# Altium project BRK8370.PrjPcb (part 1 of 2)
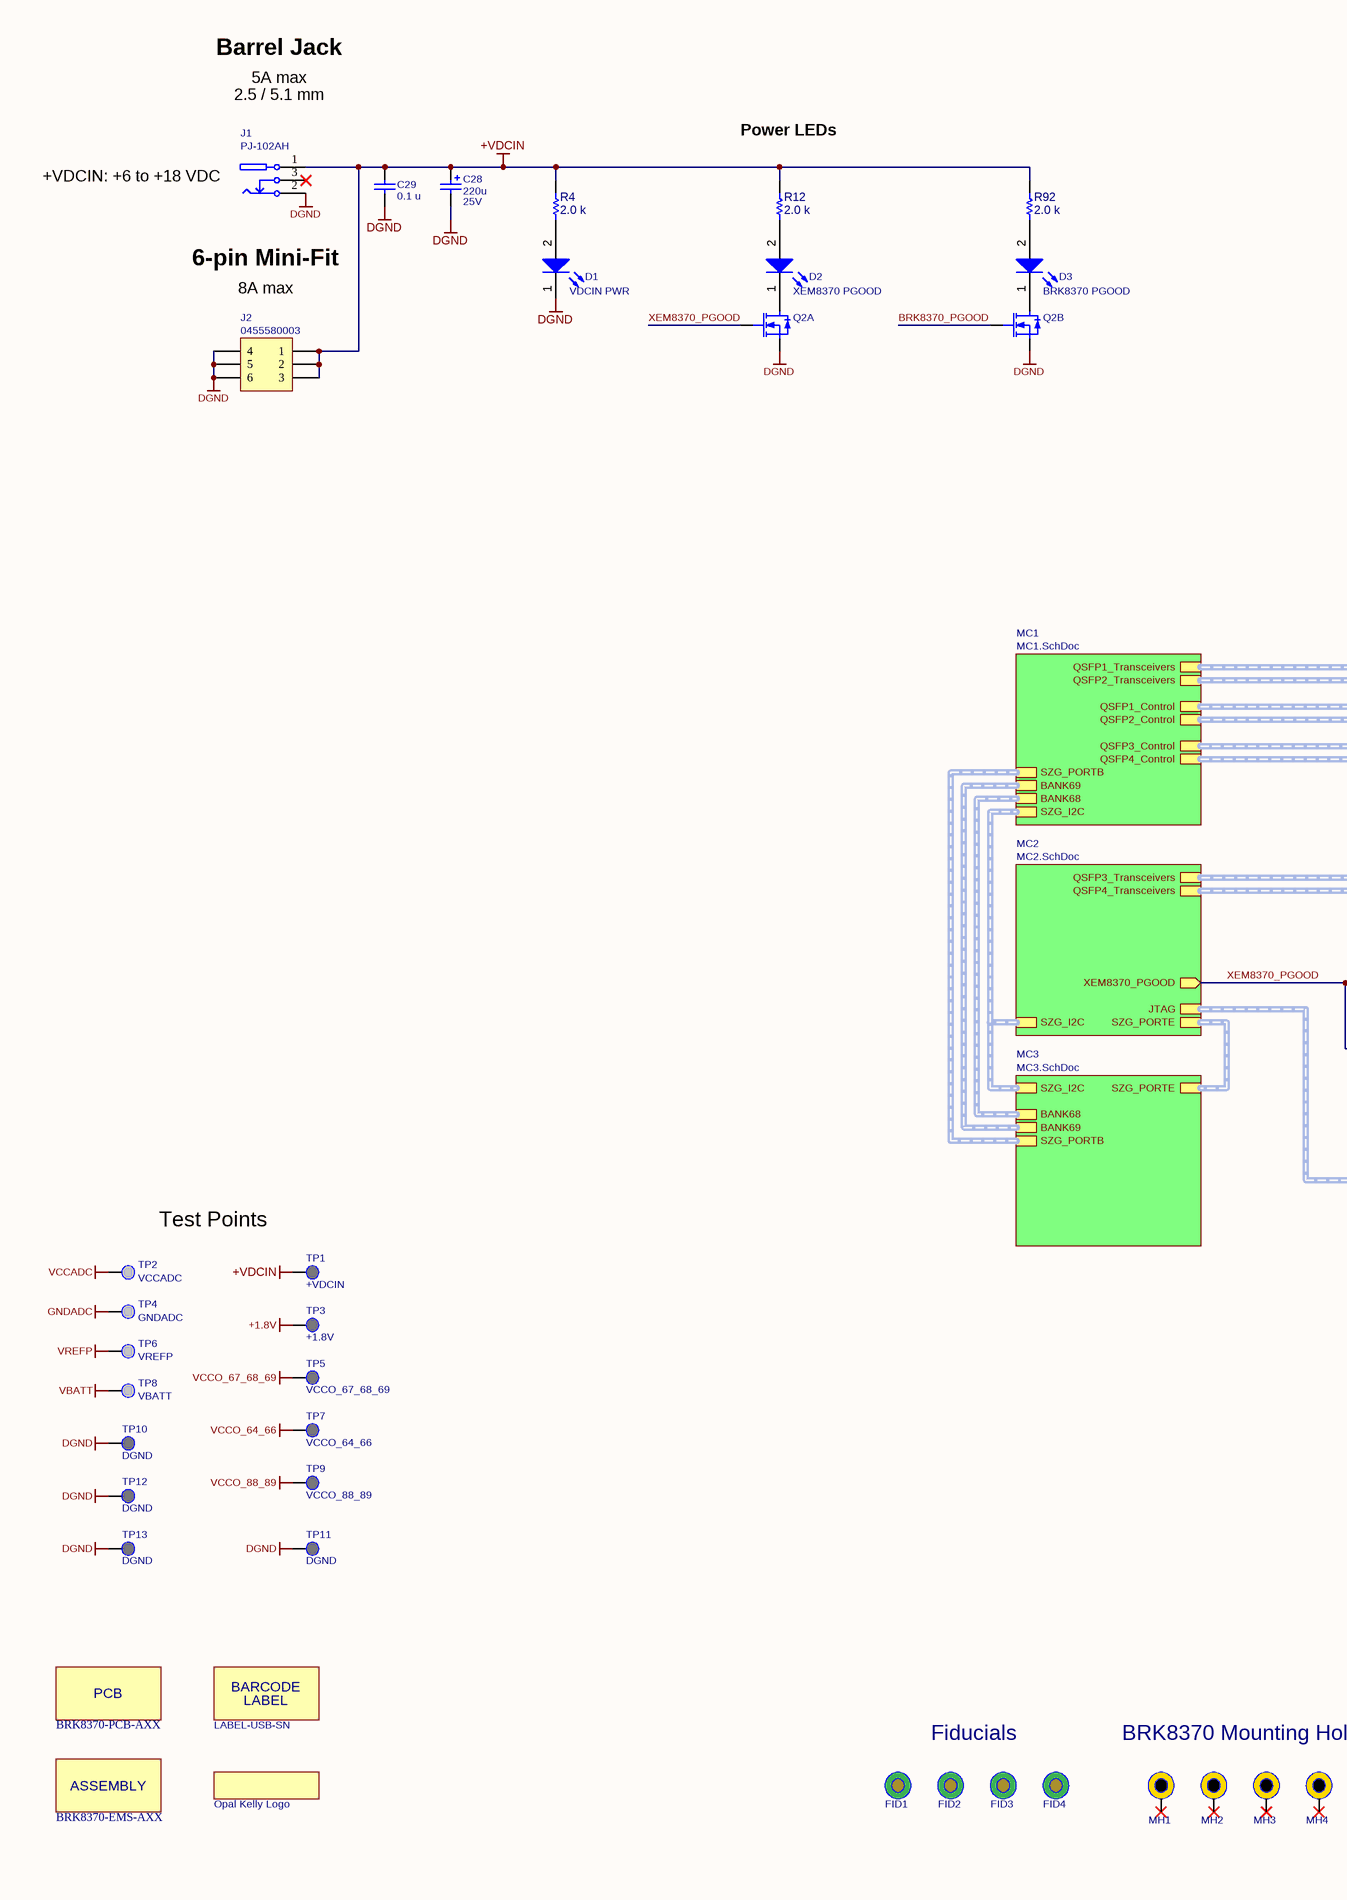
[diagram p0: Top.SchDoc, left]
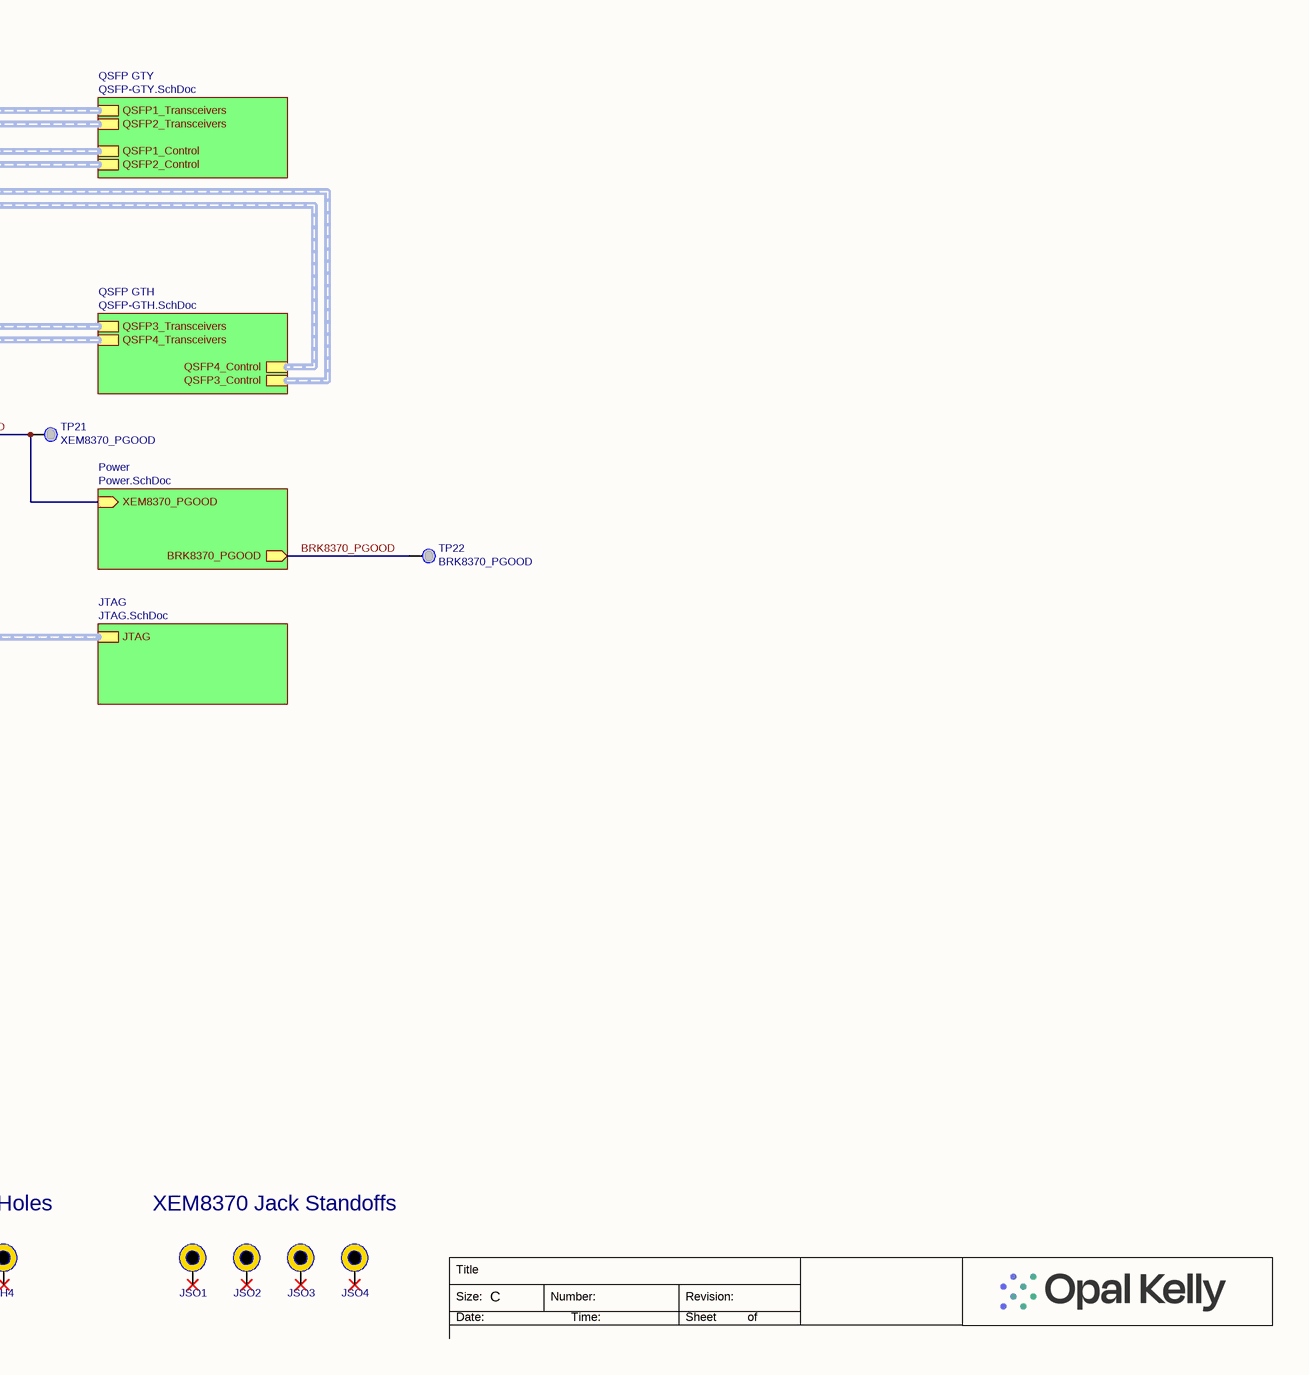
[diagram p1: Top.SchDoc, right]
PCB_Revision: A; Part_Number: BRK8370; BOM_Revision: 02
8 sheets, 322 parts. Net scope: hierarchical (ports join the sheet entries above them; power ports are global).
Board file: BRK8370.PcbDoc
Sheets:
  Top.SchDoc
    MC1 = MC1.SchDoc
    MC2 = MC2.SchDoc
    MC3 = MC3.SchDoc
    QSFP GTH = QSFP-GTH.SchDoc
    QSFP GTY = QSFP-GTY.SchDoc
    Power = Power.SchDoc
    JTAG = JTAG.SchDoc

## Sheet Top.SchDoc: BRK8370
size C; Organization: Opal Kelly; Address1: 13500 SW 72nd Ave STE 100; Address2: Portland, OR 97223; Address3: 217.391.3724; Address4: http://www.opalkelly.com; DocumentNumber: 1; Revision: 1; SheetNumber: 1; SheetTotal: 8

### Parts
ASSY1  BRK8370-EMS-AXX  (mechanical)
C28  value 220u  Voltage: 25V  [CAPAE9083X70N]  (hidden comment: EEE-FK1E221P)
C29  value 0.1 u  [CAPC1005X06A]  (hidden comment: TMK105BJ104KV-F)
D1  VDCIN PWR  [CD1608-0603-PIN1-CATHODE]
D2  XEM8370 PGOOD  [CD1608-0603-PIN1-CATHODE]
D3  BRK8370 PGOOD  [CD1608-0603-PIN1-CATHODE]
FID1  FIDUCIAL  [FID1MM/2MM-SS]  (value not drawn)
FID2  FIDUCIAL  [FID1MM/2MM-SS]  (value not drawn)
FID3  FIDUCIAL  [FID1MM/2MM-SS]  (value not drawn)
FID4  FIDUCIAL  [FID1MM/2MM-SS]  (value not drawn)
J1  PJ-102AH  [CUI-PJ102A]
J2  0455580003  [0455580003]
JSO1  Jack Screw Standoff  [JSO-0515-01]  (value not drawn)
JSO2  Jack Screw Standoff  [JSO-0515-01]  (value not drawn)
JSO3  Jack Screw Standoff  [JSO-0515-01]  (value not drawn)
JSO4  Jack Screw Standoff  [JSO-0515-01]  (value not drawn)
LABEL1  LABEL-USB-SN  (mechanical)
LOGO1  Opal Kelly Logo  [okLogo-23x5-2021]
MH1  MTG  [MTG-3.2/6.5-PTH]  (value not drawn)
MH2  MTG  [MTG-3.2/6.5-PTH]  (value not drawn)
MH3  MTG  [MTG-3.2/6.5-PTH]  (value not drawn)
MH4  MTG  [MTG-3.2/6.5-PTH]  (value not drawn)
PCB1  BRK8370-PCB-AXX  (mechanical)
Q2  SI1922EDH-T1-GE3  [SOT363-6N]  (value not drawn)  (parts A,B of 2)
R4  value 2.0 k  [RESC1005X06A]  (hidden comment: CRCW04022K00FKED)
R12  value 2.0 k  [RESC1005X06A]  (hidden comment: CRCW04022K00FKED)
R92  value 2.0 k  [RESC1005X06A]  (hidden comment: CRCW04022K00FKED)
TP1  +VDCIN  [TP-PTH-65/100]
TP2  VCCADC  [TP-PTH-25/45]
TP3  +1.8V  [TP-PTH-65/100]
TP4  GNDADC  [TP-PTH-25/45]
TP5  VCCO_67_68_69  [TP-PTH-65/100]
TP6  VREFP  [TP-PTH-25/45]
TP7  VCCO_64_66  [TP-PTH-65/100]
TP8  VBATT  [TP-PTH-25/45]
TP9  VCCO_88_89  [TP-PTH-65/100]
TP10  DGND  [TP-PTH-65/100]
TP11  DGND  [TP-PTH-65/100]
TP12  DGND  [TP-PTH-65/100]
TP13  DGND  [TP-PTH-65/100]
TP21  XEM8370_PGOOD  [TP-PTH-25/45]
TP22  BRK8370_PGOOD  [TP-PTH-25/45]

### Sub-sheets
JTAG = JTAG.SchDoc: JTAG (harness JTAG)
MC1 = MC1.SchDoc: QSFP1_Transceivers (harness QSFP_Transceivers), QSFP2_Transceivers (harness QSFP_Transceivers), QSFP1_Control (harness QSFP_Control), QSFP2_Control (harness QSFP_Control), QSFP3_Control (harness QSFP_Control), QSFP4_Control (harness QSFP_Control), BANK69 (harness BANK_69_IO), BANK68 (harness BANK_68_IO), SZG_PORTB (harness SYZYGY_PORTB), SZG_I2C (harness I2C)
MC2 = MC2.SchDoc: QSFP3_Transceivers (harness QSFP_Transceivers), QSFP4_Transceivers (harness QSFP_Transceivers), XEM8370_PGOOD (out), SZG_PORTE (harness SYZYGY_TXR4), JTAG (harness JTAG), SZG_I2C (harness I2C)
MC3 = MC3.SchDoc: SZG_I2C (harness I2C), SZG_PORTE (harness SYZYGY_TXR4), BANK69 (harness BANK_69_IO), BANK68 (harness BANK_68_IO), SZG_PORTB (harness SYZYGY_PORTB)
Power = Power.SchDoc: XEM8370_PGOOD (in), BRK8370_PGOOD (out)
QSFP GTH = QSFP-GTH.SchDoc: QSFP3_Control (harness QSFP_Control), QSFP4_Control (harness QSFP_Control), QSFP3_Transceivers (harness QSFP_Transceivers), QSFP4_Transceivers (harness QSFP_Transceivers)
QSFP GTY = QSFP-GTY.SchDoc: QSFP1_Control (harness QSFP_Control), QSFP2_Control (harness QSFP_Control), QSFP1_Transceivers (harness QSFP_Transceivers), QSFP2_Transceivers (harness QSFP_Transceivers)

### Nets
+1.8V: TP3.1(PIN)
+VDCIN: C28.1 C29.2 J1.1 J2.1 J2.2 J2.3 R4.2 R12.2 R92.2 TP1.1(PIN)
DGND: C28.2 C29.1 D1.1(K) J1.2 J2.4 J2.5 J2.6 Q2.1(S1) Q2.4(S2) TP10.1(PIN) TP11.1(PIN) TP12.1(PIN) TP13.1(PIN)
GNDADC: TP4.1(PIN)
VBATT: TP8.1(PIN)
VCCADC: TP2.1(PIN)
VCCO_64_66: TP7.1(PIN)
VCCO_67_68_69: TP5.1(PIN)
VCCO_88_89: TP9.1(PIN)
VREFP: TP6.1(PIN)
BRK8370_PGOOD: Q2.5(G2) TP22.1(PIN) ; sheet Power/BRK8370_PGOOD
XEM8370_PGOOD: Q2.2(G1) TP21.1(PIN) ; sheet MC2/XEM8370_PGOOD, sheet Power/XEM8370_PGOOD
NetD1_2: D1.2(A) R4.1
NetD2_1: D2.1(K) Q2.6(D1)
NetD2_2: D2.2(A) R12.1
NetD3_1: D3.1(K) Q2.3(D2)
NetD3_2: D3.2(A) R92.1

Not connected (* = marked no-connect by the designer): J1 3*; JSO1 1*; JSO2 1*; JSO3 1*; JSO4 1*; MH1 1*; MH2 1*; MH3 1*; MH4 1*

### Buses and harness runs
harness sheet JTAG/JTAG = sheet MC2/JTAG
harness sheet MC1/BANK68 = sheet MC3/BANK68
harness sheet MC1/BANK69 = sheet MC3/BANK69
harness sheet MC1/QSFP1_Control = sheet QSFP GTY/QSFP1_Control
harness sheet MC1/QSFP1_Transceivers = sheet QSFP GTY/QSFP1_Transceivers
harness sheet MC1/QSFP2_Control = sheet QSFP GTY/QSFP2_Control
harness sheet MC1/QSFP2_Transceivers = sheet QSFP GTY/QSFP2_Transceivers
harness sheet MC1/QSFP3_Control = sheet QSFP GTH/QSFP3_Control
harness sheet MC1/QSFP4_Control = sheet QSFP GTH/QSFP4_Control
harness sheet MC1/SZG_I2C = sheet MC2/SZG_I2C = sheet MC3/SZG_I2C
harness sheet MC1/SZG_PORTB = sheet MC3/SZG_PORTB
harness sheet MC2/QSFP3_Transceivers = sheet QSFP GTH/QSFP3_Transceivers
harness sheet MC2/QSFP4_Transceivers = sheet QSFP GTH/QSFP4_Transceivers
harness sheet MC2/SZG_PORTE = sheet MC3/SZG_PORTE

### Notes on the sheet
- Barrel Jack
- 5A max
- 2.5 / 5.1 mm
- Power LEDs
- +VDCIN: +6 to +18 VDC
- 6-pin Mini-Fit
- 8A max
- Test Points
- Fiducials
- BRK8370 Mounting Holes
- XEM8370 Jack Standoffs
- Title
- Size:
- Date:
- C
- Number:
- Time:
- Revision:
- Sheet
- of

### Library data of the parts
ASSY1 = 002536: BRK8370 PCB assembly; Partnumber: 002536; Manufacturer: PCB Assembly Cost
C28 = 001532: Polarized; Partnumber: 001532; manufacturer: Panasonic; ValueFloat: 0.00022; id: 155442; inventory_price: 0.2; x_tolerance: 20; x_voltage-rating: 25
C29 = 001073: Ceramic capacitor; Manufacturer: Taiyo Yuden; partnumber: 001073; Description 2: 0402, 25V; ValueFloat: 1E-7; Tolerance (%): 10; Voltage: 25V
D1-D3 = 001433: LED; Manufacturer: Dialight; Manufacturer_PN: 598-8070-107F; partnumber: 001433; Description 2: SM-0603, green; x_lifecycle_status: Production
FID1-FID4 = FIDUCIAL: PCB fiducial; partnumber: ALIGNI_IGNORE
J1 = DCPOWER: DC power connector - high current; manufacturer: CUI Inc.; partnumber: 000356
J2 = 001950: Partnumber: 001950; manufacturer: Molex
JSO1-JSO4 = 001879: Mounting hole; Partnumber: 001879; manufacturer: Samtec
LABEL1 = 000605: Barcode serial number labels for USB devices; Manufacturer: Techiant; partnumber: 000605; Description 2: 4-digit, all four, alphanumeric, case insensitive; x_lifecycle_status: Production
LOGO1 = OKLOGO: partnumber: ALIGNI_IGNORE
MH1-MH4 = MTG: Mounting hole; partnumber: ALIGNI_IGNORE
PCB1 = 002535: PCB for BRK8370; Partnumber: 002535; Manufacturer: Generic PCB Manufacturer
Q2 = 002018: Partnumber: 002018; manufacturer: Vishay
R4 R12 R92 = 001162: Thick-film resistor; Manufacturer: Vishay; partnumber: 001162; Description 2: SM-0402, 1%, 1/16W; ValueFloat: 2000; Tolerance (%): 1
TP1 TP3 TP5 TP7 TP9-TP13 = TP-PTH-65/100: Test point, plated through-hole, 65/100mil; partnumber: ALIGNI_IGNORE
TP2 TP4 TP6 TP8 TP21 TP22 = TP-PTH-25/45: Test point, plated through-hole, 25/45mil

## Sheet MC1.SchDoc: BRK8370 - MC1
size C; Organization: Opal Kelly; Address1: 13500 SW 72nd Ave STE 100; Address2: Portland, OR 97223; Address3: 217.391.3724; Address4: http://www.opalkelly.com; DocumentNumber: 2; Revision: 1; SheetNumber: 2; SheetTotal: 8
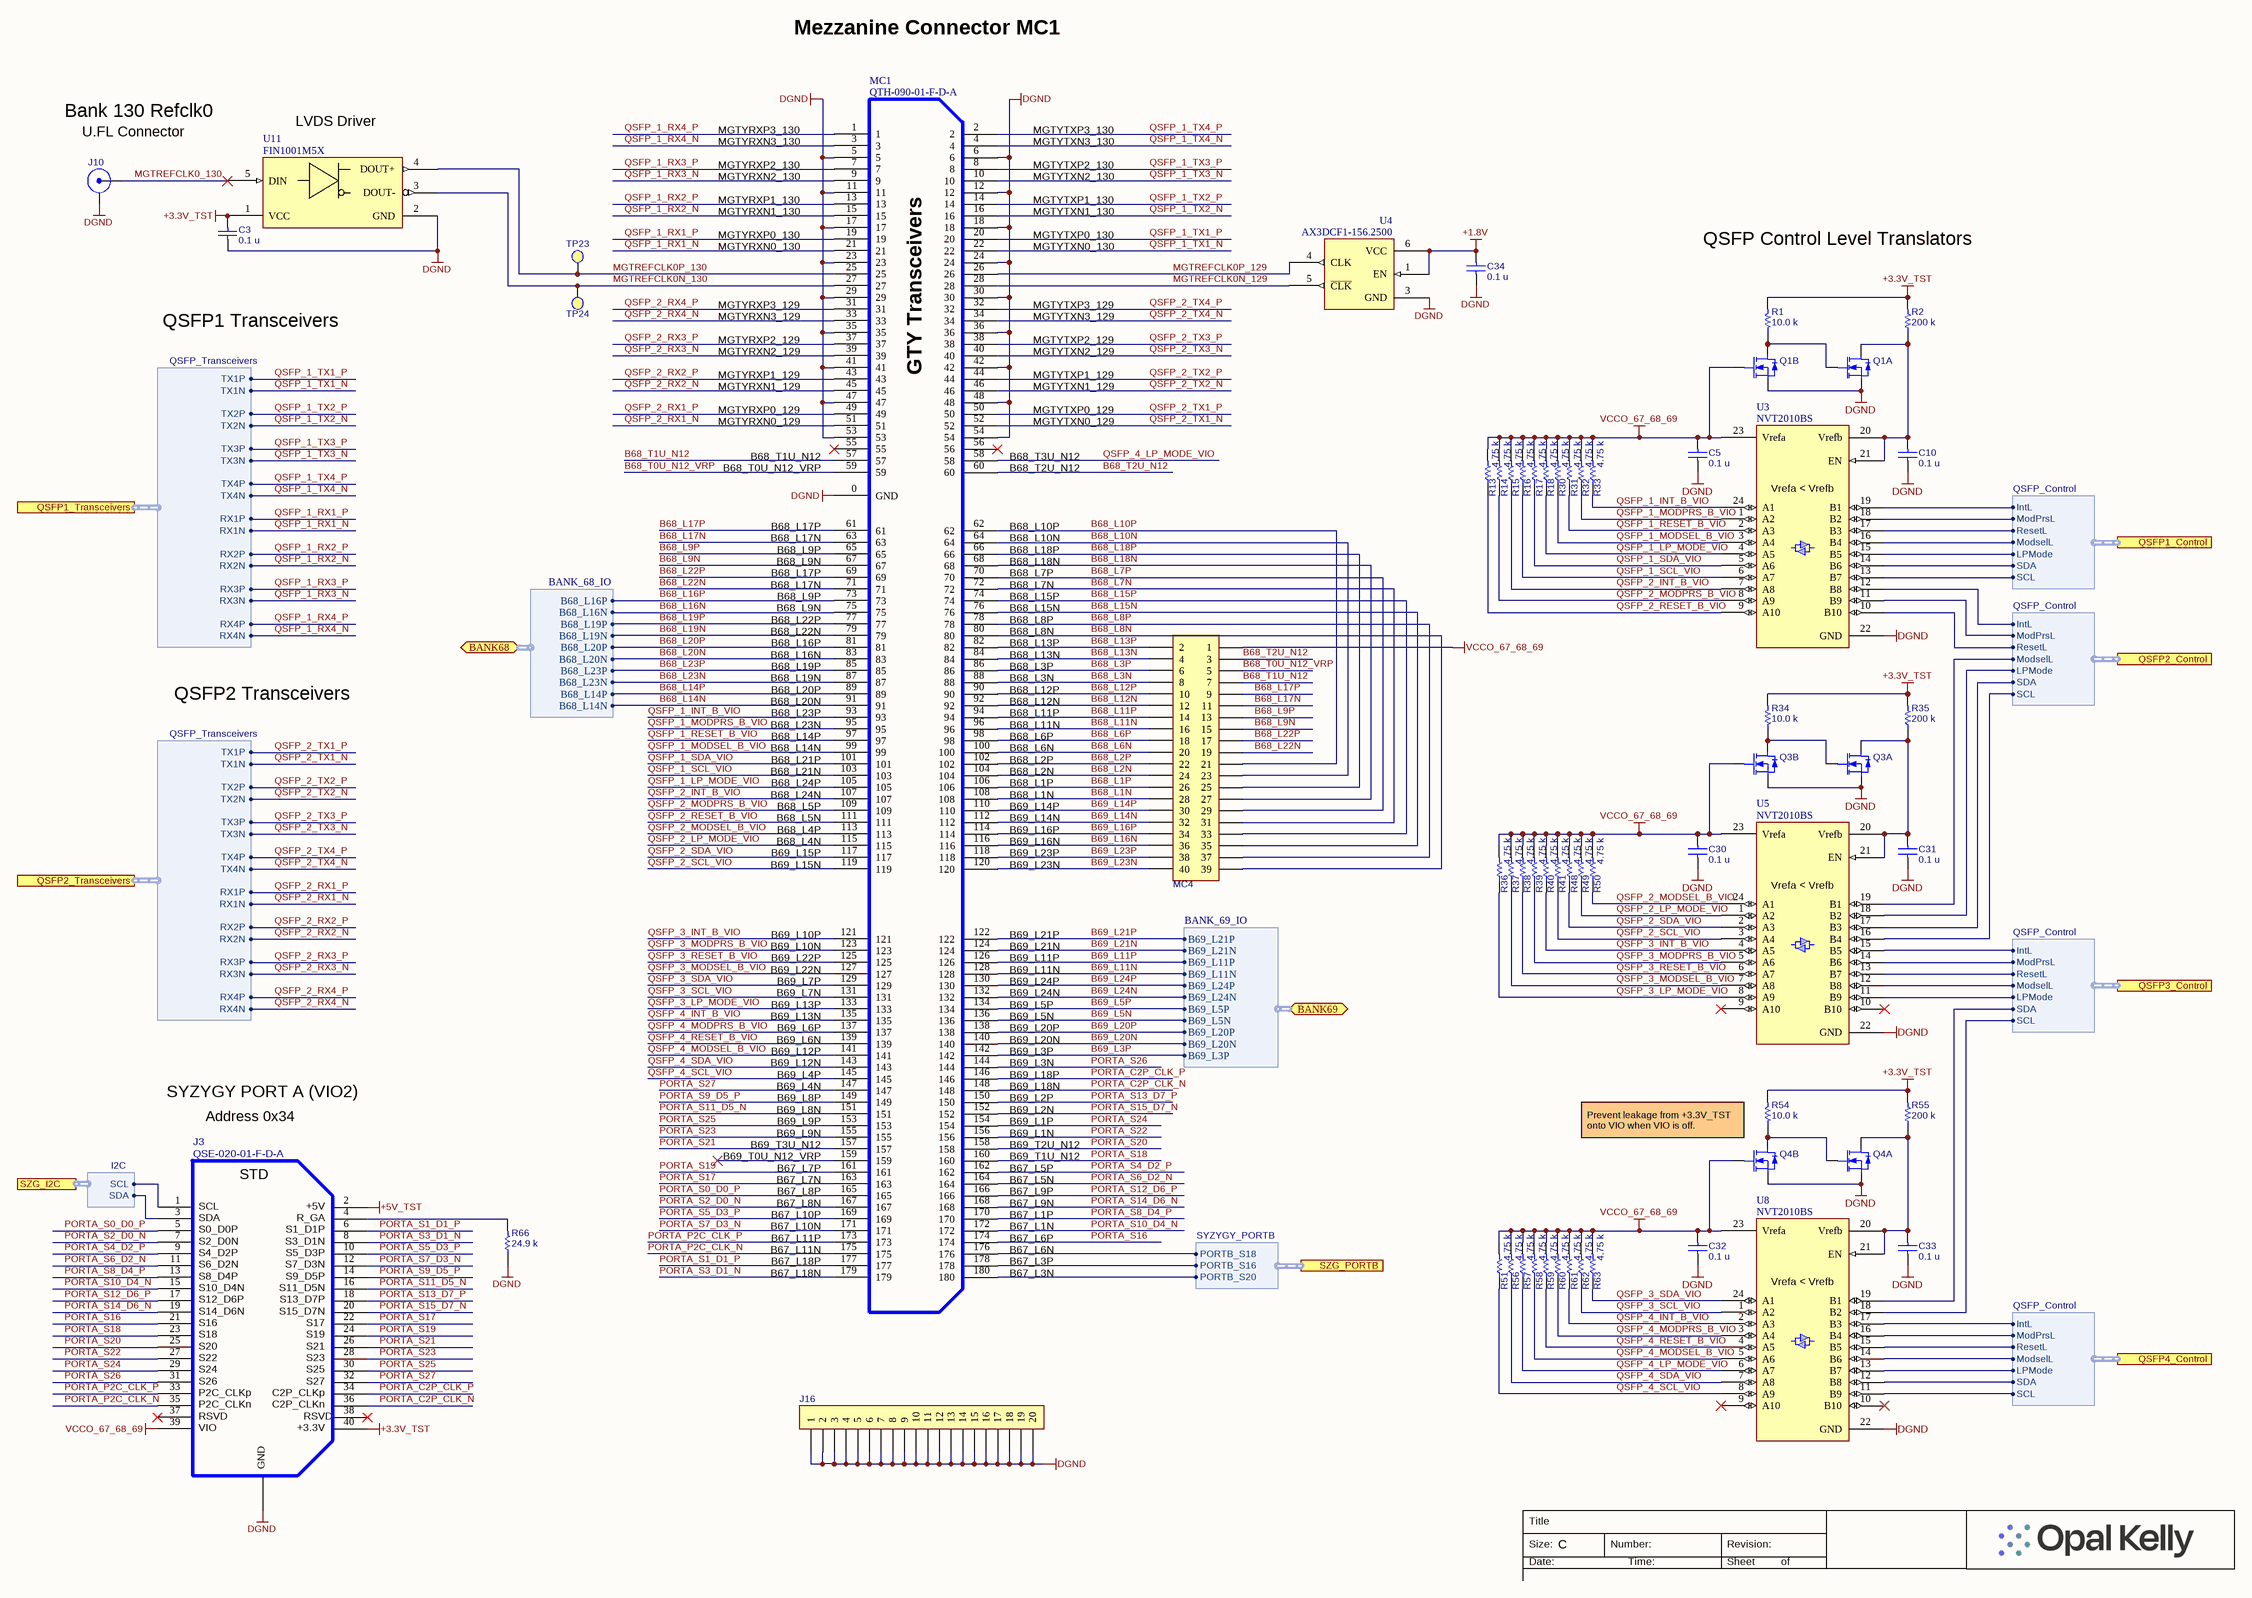
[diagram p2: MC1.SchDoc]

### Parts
C3  value 0.1 u  [CAPC1005X06A]  (hidden comment: SM-0402, 10%, 10v)
C5  value 0.1 u  [CAPC1005X06A]  (hidden comment: SM-0402, 10%, 10v)
C10  value 0.1 u  [CAPC1005X06A]  (hidden comment: SM-0402, 10%, 10v)
C30  value 0.1 u  [CAPC1005X06A]  (hidden comment: SM-0402, 10%, 10v)
C31  value 0.1 u  [CAPC1005X06A]  (hidden comment: SM-0402, 10%, 10v)
C32  value 0.1 u  [CAPC1005X06A]  (hidden comment: SM-0402, 10%, 10v)
C33  value 0.1 u  [CAPC1005X06A]  (hidden comment: SM-0402, 10%, 10v)
C34  value 0.1 u  [CAPC1005X06A]  (hidden comment: SM-0402, 10%, 10v)
J3  QSE-020-01-F-D-A  [QSE-020-01-X-D-A-L-SYZYGY]
J10  RXP0  [UFL-R-SMT-1]  (value not drawn)
J16  Header, 20-Pin, Single Row  [HDR1X20-2MM]  (value not drawn)
MC1  QTH-090-01-F-D-A  [QTH-090-01-X-D]
MC4  0877584016  [HDR2X20-2MM]  (value not drawn)
Q1  SI1922EDH-T1-GE3  [SOT363-6N]  (value not drawn)  (parts A,B of 2)
Q3  SI1922EDH-T1-GE3  [SOT363-6N]  (value not drawn)  (parts A,B of 2)
Q4  SI1922EDH-T1-GE3  [SOT363-6N]  (value not drawn)  (parts A,B of 2)
R1  value 10.0 k  [RESC1005X06A]  (hidden comment: CRCW040210K0FKED)
R2  value 200 k  [RESC1005X06A]  (hidden comment: CRCW0402200KFKED)
R13  value 4.75 k  [RESC1005X06A]  (hidden comment: CRCW04024K75FKED)
R14  value 4.75 k  [RESC1005X06A]  (hidden comment: CRCW04024K75FKED)
R15  value 4.75 k  [RESC1005X06A]  (hidden comment: CRCW04024K75FKED)
R16  value 4.75 k  [RESC1005X06A]  (hidden comment: CRCW04024K75FKED)
R17  value 4.75 k  [RESC1005X06A]  (hidden comment: CRCW04024K75FKED)
R18  value 4.75 k  [RESC1005X06A]  (hidden comment: CRCW04024K75FKED)
R30  value 4.75 k  [RESC1005X06A]  (hidden comment: CRCW04024K75FKED)
R31  value 4.75 k  [RESC1005X06A]  (hidden comment: CRCW04024K75FKED)
R32  value 4.75 k  [RESC1005X06A]  (hidden comment: CRCW04024K75FKED)
R33  value 4.75 k  [RESC1005X06A]  (hidden comment: CRCW04024K75FKED)
R34  value 10.0 k  [RESC1005X06A]  (hidden comment: CRCW040210K0FKED)
R35  value 200 k  [RESC1005X06A]  (hidden comment: CRCW0402200KFKED)
R36  value 4.75 k  [RESC1005X06A]  (hidden comment: CRCW04024K75FKED)
R37  value 4.75 k  [RESC1005X06A]  (hidden comment: CRCW04024K75FKED)
R38  value 4.75 k  [RESC1005X06A]  (hidden comment: CRCW04024K75FKED)
R39  value 4.75 k  [RESC1005X06A]  (hidden comment: CRCW04024K75FKED)
R40  value 4.75 k  [RESC1005X06A]  (hidden comment: CRCW04024K75FKED)
R41  value 4.75 k  [RESC1005X06A]  (hidden comment: CRCW04024K75FKED)
R48  value 4.75 k  [RESC1005X06A]  (hidden comment: CRCW04024K75FKED)
R49  value 4.75 k  [RESC1005X06A]  (hidden comment: CRCW04024K75FKED)
R50  value 4.75 k  [RESC1005X06A]  (hidden comment: CRCW04024K75FKED)
R51  value 4.75 k  [RESC1005X06A]  (hidden comment: CRCW04024K75FKED)
R54  value 10.0 k  [RESC1005X06A]  (hidden comment: CRCW040210K0FKED)
R55  value 200 k  [RESC1005X06A]  (hidden comment: CRCW0402200KFKED)
R56  value 4.75 k  [RESC1005X06A]  (hidden comment: CRCW04024K75FKED)
R57  value 4.75 k  [RESC1005X06A]  (hidden comment: CRCW04024K75FKED)
R58  value 4.75 k  [RESC1005X06A]  (hidden comment: CRCW04024K75FKED)
R59  value 4.75 k  [RESC1005X06A]  (hidden comment: CRCW04024K75FKED)
R60  value 4.75 k  [RESC1005X06A]  (hidden comment: CRCW04024K75FKED)
R61  value 4.75 k  [RESC1005X06A]  (hidden comment: CRCW04024K75FKED)
R62  value 4.75 k  [RESC1005X06A]  (hidden comment: CRCW04024K75FKED)
R63  value 4.75 k  [RESC1005X06A]  (hidden comment: CRCW04024K75FKED)
R66  value 24.9 k  [RESC1005X06A]  (hidden comment: CRCW040224K9FKED)
TP23  TESTPOINT-SMD20  [TP-SMD20]  (value not drawn)
TP24  TESTPOINT-SMD20  [TP-SMD20]  (value not drawn)
U3  NVT2010BS  [QFN-24]
U4  AX3DCF1-156.2500  [OSC_SMD_32x25_6pin]
U5  NVT2010BS  [QFN-24]
U8  NVT2010BS  [QFN-24]
U11  FIN1001M5X  [SOT23-5]

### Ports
BANK68 (bidir, harness BANK_68_IO), BANK69 (bidir, harness BANK_69_IO), QSFP1_Control (harness QSFP_Control), QSFP1_Transceivers (harness QSFP_Transceivers), QSFP2_Control (harness QSFP_Control), QSFP2_Transceivers (harness QSFP_Transceivers), QSFP3_Control (harness QSFP_Control), QSFP4_Control (harness QSFP_Control), SZG_I2C (harness I2C), SZG_PORTB (harness SYZYGY_PORTB)

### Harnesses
QSFP_Transceivers: TX1P, TX1N, TX2P, TX2N, TX3P, TX3N, TX4P, TX4N, RX1P, RX1N, RX2P, RX2N, RX3P, RX3N, RX4P, RX4N
QSFP_Control: ModPrsL, IntL, LPMode, ModselL, ResetL, SCL, SDA
I2C: SCL, SDA
BANK_69_IO: B69_L21P, B69_L21N, B69_L11P, B69_L11N, B69_L24P, B69_L24N, B69_L5P, B69_L5N, B69_L20P, B69_L20N, B69_L3P
BANK_68_IO: B68_L20P, B68_L20N, B68_L23P, B68_L23N, B68_L14P, B68_L14N, B68_L16P, B68_L16N, B68_L19P, B68_L19N
SYZYGY_PORTB: PORTB_S20, PORTB_S16, PORTB_S18

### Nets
+1.8V: C34.2 U4.1(EN) U4.6(VCC)
+3.3V_TST: C3.2 J3.40 R1.2 R2.2 R34.2 R35.2 R54.2 R55.2 U11.1(VCC)
+5V_TST: J3.2
DGND: C3.1 C5.1 C10.1 C30.1 C31.1 C32.1 C33.1 C34.1 J3.0 J10.2(GND) J16.1 J16.2 J16.3 J16.4 J16.5 J16.6 J16.7 J16.8 J16.9 J16.10 J16.11 J16.12 J16.13 J16.14 J16.15 J16.16 J16.17 J16.18 J16.19 J16.20 MC1.0(GND) MC1.5 MC1.6 MC1.11 MC1.12 MC1.17 MC1.18 MC1.23 MC1.24 MC1.29 MC1.30 MC1.35 MC1.36 MC1.41 MC1.42 MC1.47 MC1.48 MC1.53 MC1.54 Q1.1(S1) Q1.4(S2) Q3.1(S1) Q3.4(S2) Q4.1(S1) Q4.4(S2) R66.1 U3.22(GND) U4.3(GND) U5.22(GND) U8.22(GND) U11.2(GND)
VCCO_67_68_69: C5.2 C30.2 C32.2 J3.39 MC4.1 Q1.5(G2) Q3.5(G2) Q4.5(G2) R13.2 R14.2 R15.2 R16.2 R17.2 R18.2 R30.2 R31.2 R32.2 R33.2 R36.2 R37.2 R38.2 R39.2 R40.2 R41.2 R48.2 R49.2 R50.2 R51.2 R56.2 R57.2 R58.2 R59.2 R60.2 R61.2 R62.2 R63.2 U3.23(Vrefa) U5.23(Vrefa) U8.23(Vrefa)
B68_L1N: MC1.108 MC4.28
B68_L1P: MC1.106 MC4.26
B68_L2N: MC1.104 MC4.24
B68_L2P: MC1.102 MC4.22
B68_L3N: MC1.88 MC4.8
B68_L3P: MC1.86 MC4.6
B68_L6N: MC1.100 MC4.20
B68_L6P: MC1.98 MC4.18
B68_L7N: MC1.72 MC4.31
B68_L7P: MC1.70 MC4.29
B68_L8N: MC1.80 MC4.39
B68_L8P: MC1.78 MC4.37
B68_L9N: MC1.67 MC4.15
B68_L9P: MC1.65 MC4.13
B68_L10N: MC1.64 MC4.23
B68_L10P: MC1.62 MC4.21
B68_L11N: MC1.96 MC4.16
B68_L11P: MC1.94 MC4.14
B68_L12N: MC1.92 MC4.12
B68_L12P: MC1.90 MC4.10
B68_L13N: MC1.84 MC4.4
B68_L13P: MC1.82 MC4.2
B68_L14N: MC1.91 ; port BANK68.B68_L14N
B68_L14P: MC1.89 ; port BANK68.B68_L14P
B68_L15N: MC1.76 MC4.35
B68_L15P: MC1.74 MC4.33
B68_L16N: MC1.75 ; port BANK68.B68_L16N
B68_L16P: MC1.73 ; port BANK68.B68_L16P
B68_L17N: MC1.63 MC4.11
B68_L17P: MC1.61 MC4.9
B68_L18N: MC1.68 MC4.27
B68_L18P: MC1.66 MC4.25
B68_L19N: MC1.79 ; port BANK68.B68_L19N
B68_L19P: MC1.77 ; port BANK68.B68_L19P
B68_L20N: MC1.83 ; port BANK68.B68_L20N
B68_L20P: MC1.81 ; port BANK68.B68_L20P
B68_L22N: MC1.71 MC4.19
B68_L22P: MC1.69 MC4.17
B68_L23N: MC1.87 ; port BANK68.B68_L23N
B68_L23P: MC1.85 ; port BANK68.B68_L23P
B68_T0U_N12_VRP: MC1.59 MC4.5
B68_T1U_N12: MC1.57 MC4.7
B68_T2U_N12: MC1.60 MC4.3
B69_L3P: MC1.142 ; port BANK69.B69_L3P
B69_L5N: MC1.136 ; port BANK69.B69_L5N
B69_L5P: MC1.134 ; port BANK69.B69_L5P
B69_L11N: MC1.128 ; port BANK69.B69_L11N
B69_L11P: MC1.126 ; port BANK69.B69_L11P
B69_L14N: MC1.112 MC4.32
B69_L14P: MC1.110 MC4.30
B69_L16N: MC1.116 MC4.36
B69_L16P: MC1.114 MC4.34
B69_L20N: MC1.140 ; port BANK69.B69_L20N
B69_L20P: MC1.138 ; port BANK69.B69_L20P
B69_L21N: MC1.124 ; port BANK69.B69_L21N
B69_L21P: MC1.122 ; port BANK69.B69_L21P
B69_L23N: MC1.120 MC4.40
B69_L23P: MC1.118 MC4.38
B69_L24N: MC1.132 ; port BANK69.B69_L24N
B69_L24P: MC1.130 ; port BANK69.B69_L24P
MGTREFCLK0_130: J10.1(SIGNAL) U11.5(DIN)
MGTREFCLK0N_129: MC1.28 U4.5(~{CLK})
MGTREFCLK0N_130: MC1.27 TP24.1(PIN) U11.3(DOUT-)
MGTREFCLK0P_129: MC1.26 U4.4(CLK)
MGTREFCLK0P_130: MC1.25 TP23.1(PIN) U11.4(DOUT+)
PORTA_C2P_CLK_N: J3.36 MC1.148
PORTA_C2P_CLK_P: J3.34 MC1.146
PORTA_P2C_CLK_N: J3.35 MC1.175
PORTA_P2C_CLK_P: J3.33 MC1.173
PORTA_S0_D0_P: J3.5 MC1.165
PORTA_S1_D1_P: J3.6 MC1.177
PORTA_S2_D0_N: J3.7 MC1.167
PORTA_S3_D1_N: J3.8 MC1.179
PORTA_S4_D2_P: J3.9 MC1.162
PORTA_S5_D3_P: J3.10 MC1.169
PORTA_S6_D2_N: J3.11 MC1.164
PORTA_S7_D3_N: J3.12 MC1.171
PORTA_S8_D4_P: J3.13 MC1.170
PORTA_S9_D5_P: J3.14 MC1.149
PORTA_S10_D4_N: J3.15 MC1.172
PORTA_S11_D5_N: J3.16 MC1.151
PORTA_S12_D6_P: J3.17 MC1.166
PORTA_S13_D7_P: J3.18 MC1.150
PORTA_S14_D6_N: J3.19 MC1.168
PORTA_S15_D7_N: J3.20 MC1.152
PORTA_S16: J3.21 MC1.174
PORTA_S17: J3.22 MC1.163
PORTA_S18: J3.23 MC1.160
PORTA_S19: J3.24 MC1.161
PORTA_S20: J3.25 MC1.158
PORTA_S21: J3.26 MC1.157
PORTA_S22: J3.27 MC1.156
PORTA_S23: J3.28 MC1.155
PORTA_S24: J3.29 MC1.154
PORTA_S25: J3.30 MC1.153
PORTA_S26: J3.31 MC1.144
PORTA_S27: J3.32 MC1.147
PORTB_S16: MC1.178 ; port SZG_PORTB.PORTB_S16
PORTB_S18: MC1.176 ; port SZG_PORTB.PORTB_S18
PORTB_S20: MC1.180 ; port SZG_PORTB.PORTB_S20
QSFP_1_INT_B_3V3: U3.19(B1) ; port QSFP1_Control.IntL
QSFP_1_INT_B_VIO: MC1.93 R33.1 U3.24(A1)
QSFP_1_LP_MODE_3V3: U3.15(B5) ; port QSFP1_Control.LPMode
QSFP_1_LP_MODE_VIO: MC1.105 R18.1 U3.4(A5)
QSFP_1_MODPRS_B_3V3: U3.18(B2) ; port QSFP1_Control.ModPrsL
QSFP_1_MODPRS_B_VIO: MC1.95 R32.1 U3.1(A2)
QSFP_1_MODSEL_B_3V3: U3.16(B4) ; port QSFP1_Control.ModselL
QSFP_1_MODSEL_B_VIO: MC1.99 R30.1 U3.3(A4)
QSFP_1_RESET_B_3V3: U3.17(B3) ; port QSFP1_Control.ResetL
QSFP_1_RESET_B_VIO: MC1.97 R31.1 U3.2(A3)
QSFP_1_RX1_N: MC1.21 ; port QSFP1_Transceivers.RX1N
QSFP_1_RX1_P: MC1.19 ; port QSFP1_Transceivers.RX1P
QSFP_1_RX2_N: MC1.15 ; port QSFP1_Transceivers.RX2N
QSFP_1_RX2_P: MC1.13 ; port QSFP1_Transceivers.RX2P
QSFP_1_RX3_N: MC1.9 ; port QSFP1_Transceivers.RX3N
QSFP_1_RX3_P: MC1.7 ; port QSFP1_Transceivers.RX3P
QSFP_1_RX4_N: MC1.3 ; port QSFP1_Transceivers.RX4N
QSFP_1_RX4_P: MC1.1 ; port QSFP1_Transceivers.RX4P
QSFP_1_SCL_3V3: U3.13(B7) ; port QSFP1_Control.SCL
QSFP_1_SCL_VIO: MC1.103 R16.1 U3.6(A7)
QSFP_1_SDA_3V3: U3.14(B6) ; port QSFP1_Control.SDA
QSFP_1_SDA_VIO: MC1.101 R17.1 U3.5(A6)
QSFP_1_TX1_N: MC1.22 ; port QSFP1_Transceivers.TX1N
QSFP_1_TX1_P: MC1.20 ; port QSFP1_Transceivers.TX1P
QSFP_1_TX2_N: MC1.16 ; port QSFP1_Transceivers.TX2N
QSFP_1_TX2_P: MC1.14 ; port QSFP1_Transceivers.TX2P
QSFP_1_TX3_N: MC1.10 ; port QSFP1_Transceivers.TX3N
QSFP_1_TX3_P: MC1.8 ; port QSFP1_Transceivers.TX3P
QSFP_1_TX4_N: MC1.4 ; port QSFP1_Transceivers.TX4N
QSFP_1_TX4_P: MC1.2 ; port QSFP1_Transceivers.TX4P
QSFP_2_INT_B_3V3: U3.12(B8) ; port QSFP2_Control.IntL
QSFP_2_INT_B_VIO: MC1.107 R15.1 U3.7(A8)
QSFP_2_LP_MODE_3V3: U5.18(B2) ; port QSFP2_Control.LPMode
QSFP_2_LP_MODE_VIO: MC1.115 R49.1 U5.1(A2)
QSFP_2_MODPRS_B_3V3: U3.11(B9) ; port QSFP2_Control.ModPrsL
QSFP_2_MODPRS_B_VIO: MC1.109 R14.1 U3.8(A9)
QSFP_2_MODSEL_B_3V3: U5.19(B1) ; port QSFP2_Control.ModselL
QSFP_2_MODSEL_B_VIO: MC1.113 R50.1 U5.24(A1)
QSFP_2_RESET_B_3V3: U3.10(B10) ; port QSFP2_Control.ResetL
QSFP_2_RESET_B_VIO: MC1.111 R13.1 U3.9(A10)
QSFP_2_RX1_N: MC1.51 ; port QSFP2_Transceivers.RX1N
QSFP_2_RX1_P: MC1.49 ; port QSFP2_Transceivers.RX1P
QSFP_2_RX2_N: MC1.45 ; port QSFP2_Transceivers.RX2N
QSFP_2_RX2_P: MC1.43 ; port QSFP2_Transceivers.RX2P
QSFP_2_RX3_N: MC1.39 ; port QSFP2_Transceivers.RX3N
QSFP_2_RX3_P: MC1.37 ; port QSFP2_Transceivers.RX3P
QSFP_2_RX4_N: MC1.33 ; port QSFP2_Transceivers.RX4N
QSFP_2_RX4_P: MC1.31 ; port QSFP2_Transceivers.RX4P
QSFP_2_SCL_3V3: U5.16(B4) ; port QSFP2_Control.SCL
QSFP_2_SCL_VIO: MC1.119 R41.1 U5.3(A4)
QSFP_2_SDA_3V3: U5.17(B3) ; port QSFP2_Control.SDA
QSFP_2_SDA_VIO: MC1.117 R48.1 U5.2(A3)
QSFP_2_TX1_N: MC1.52 ; port QSFP2_Transceivers.TX1N
QSFP_2_TX1_P: MC1.50 ; port QSFP2_Transceivers.TX1P
QSFP_2_TX2_N: MC1.46 ; port QSFP2_Transceivers.TX2N
QSFP_2_TX2_P: MC1.44 ; port QSFP2_Transceivers.TX2P
QSFP_2_TX3_N: MC1.40 ; port QSFP2_Transceivers.TX3N
QSFP_2_TX3_P: MC1.38 ; port QSFP2_Transceivers.TX3P
QSFP_2_TX4_N: MC1.34 ; port QSFP2_Transceivers.TX4N
QSFP_2_TX4_P: MC1.32 ; port QSFP2_Transceivers.TX4P
QSFP_3_INT_B_3V3: U5.15(B5) ; port QSFP3_Control.IntL
QSFP_3_INT_B_VIO: MC1.121 R40.1 U5.4(A5)
QSFP_3_LP_MODE_3V3: U5.11(B9) ; port QSFP3_Control.LPMode
QSFP_3_LP_MODE_VIO: MC1.133 R36.1 U5.8(A9)
QSFP_3_MODPRS_B_3V3: U5.14(B6) ; port QSFP3_Control.ModPrsL
QSFP_3_MODPRS_B_VIO: MC1.123 R39.1 U5.5(A6)
QSFP_3_MODSEL_B_3V3: U5.12(B8) ; port QSFP3_Control.ModselL
QSFP_3_MODSEL_B_VIO: MC1.127 R37.1 U5.7(A8)
QSFP_3_RESET_B_3V3: U5.13(B7) ; port QSFP3_Control.ResetL
QSFP_3_RESET_B_VIO: MC1.125 R38.1 U5.6(A7)
QSFP_3_SCL_3V3: U8.18(B2) ; port QSFP3_Control.SCL
QSFP_3_SCL_VIO: MC1.131 R62.1 U8.1(A2)
QSFP_3_SDA_3V3: U8.19(B1) ; port QSFP3_Control.SDA
QSFP_3_SDA_VIO: MC1.129 R63.1 U8.24(A1)
QSFP_4_INT_B_3V3: U8.17(B3) ; port QSFP4_Control.IntL
QSFP_4_INT_B_VIO: MC1.135 R61.1 U8.2(A3)
QSFP_4_LP_MODE_3V3: U8.13(B7) ; port QSFP4_Control.LPMode
QSFP_4_LP_MODE_VIO: MC1.58 R57.1 U8.6(A7)
QSFP_4_MODPRS_B_3V3: U8.16(B4) ; port QSFP4_Control.ModPrsL
QSFP_4_MODPRS_B_VIO: MC1.137 R60.1 U8.3(A4)
QSFP_4_MODSEL_B_3V3: U8.14(B6) ; port QSFP4_Control.ModselL
QSFP_4_MODSEL_B_VIO: MC1.141 R58.1 U8.5(A6)
QSFP_4_RESET_B_3V3: U8.15(B5) ; port QSFP4_Control.ResetL
QSFP_4_RESET_B_VIO: MC1.139 R59.1 U8.4(A5)
QSFP_4_SCL_3V3: U8.11(B9) ; port QSFP4_Control.SCL
QSFP_4_SCL_VIO: MC1.145 R51.1 U8.8(A9)
QSFP_4_SDA_3V3: U8.12(B8) ; port QSFP4_Control.SDA
QSFP_4_SDA_VIO: MC1.143 R56.1 U8.7(A8)
SZG_SCL_3V3: J3.1 ; port SZG_I2C.SCL
SZG_SDA_3V3: J3.3 ; port SZG_I2C.SDA
NetC10_2: C10.2 Q1.6(D1) R2.1 U3.20(Vrefb) U3.21(EN)
NetC31_2: C31.2 Q3.6(D1) R35.1 U5.20(Vrefb) U5.21(EN)
NetC33_2: C33.2 Q4.6(D1) R55.1 U8.20(Vrefb) U8.21(EN)
NetJ3_4: J3.4 R66.2
NetQ1_2: Q1.2(G1) Q1.3(D2) R1.1
NetQ3_2: Q3.2(G1) Q3.3(D2) R34.1
NetQ4_2: Q4.2(G1) Q4.3(D2) R54.1

Not connected (* = marked no-connect by the designer): J3 37* 38*; MC1 55* 56* 159*; U5 9(A10)* 10(B10)*; U8 9(A10)* 10(B10)*

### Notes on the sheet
- Mezzanine Connector MC1
- Bank 130 Refclk0
- (near J10) U.FL Connector
- (near U11) LVDS Driver
- (near MC1) GTY Transceivers
- QSFP Control Level Translators
- QSFP1 Transceivers
- MGTYRXP3_130
  MGTYRXN3_130
  MGTYRXP2_130
  MGTYRXN2_130
  MGTYRXP1_130
  MGTYRXN1_130
  MGTYRXP0_130
  MGTYRXN0_130
  MGTYRXP3_129
  MGTYRXN3_129
  MGTYRXP2_129
  MGTYRXN2_129
  MGTYRXP1_129
  MGTYRXN1_129
  MGTYRXP0_129
  MGTYRXN0_129
- MGTYTXP3_130
  MGTYTXN3_130
  MGTYTXP2_130
  MGTYTXN2_130
  MGTYTXP1_130
  MGTYTXN1_130
  MGTYTXP0_130
  MGTYTXN0_130
  MGTYTXP3_129
  MGTYTXN3_129
  MGTYTXP2_129
  MGTYTXN2_129
  MGTYTXP1_129
  MGTYTXN1_129
  MGTYTXP0_129
  MGTYTXN0_129
- QSFP2 Transceivers
- SYZYGY PORT A (VIO2)
- Address 0x34
- (near Q4) Prevent leakage from +3.3V_TST onto VIO when VIO is off.
- B68_T1U_N12
  B68_T0U_N12_VRP
  B68_L17P
  B68_L17N
  B68_L9P
  B68_L9N
  B68_L17P
  B68_L17N
  B68_L9P
  B68_L9N
  B68_L22P
  B68_L22N
  B68_L16P
  B68_L16N
  B68_L19P
  B68_L19N
  B68_L20P
  B68_L20N
  B68_L23P
  B68_L23N
  B68_L14P
  B68_L14N
  B68_L21P
  B68_L21N
  B68_L24P
  B68_L24N
  B68_L5P
  B68_L5N
  B68_L4P
  B68_L4N
  B69_L15P
  B69_L15N
  B69_L10P
  B69_L10N
  B69_L22P
  B69_L22N
  B69_L7P
  B69_L7N
  B69_L13P
  B69_L13N
  B69_L6P
  B69_L6N
  B69_L12P
  B69_L12N
  B69_L4P
  B69_L4N
  B69_L8P
  B69_L8N
  B69_L9P
  B69_L9N
  B69_T3U_N12
  B69_T0U_N12_VRP
  B67_L7P
  B67_L7N
  B67_L8P
  B67_L8N
  B67_L10P
  B67_L10N
  B67_L11P
  B67_L11N
  B67_L18P
  B67_L18N
- B68_T3U_N12
  B68_T2U_N12
  B68_L10P
  B68_L10N
  B68_L18P
  B68_L18N
  B68_L7P
  B68_L7N
  B68_L15P
  B68_L15N
  B68_L8P
  B68_L8N
  B68_L13P
  B68_L13N
  B68_L3P
  B68_L3N
  B68_L12P
  B68_L12N
  B68_L11P
  B68_L11N
  B68_L6P
  B68_L6N
  B68_L2P
  B68_L2N
  B68_L1P
  B68_L1N
  B69_L14P
  B69_L14N
  B69_L16P
  B69_L16N
  B69_L23P
  B69_L23N
  B69_L21P
  B69_L21N
  B69_L11P
  B69_L11N
  B69_L24P
  B69_L24N
  B69_L5P
  B69_L5N
  B69_L20P
  B69_L20N
  B69_L3P
  B69_L3N
  B69_L18P
  B69_L18N
  B69_L2P
  B69_L2N
  B69_L1P
  B69_L1N
  B69_T2U_N12
  B69_T1U_N12
  B67_L5P
  B67_L5N
  B67_L9P
  B67_L9N
  B67_L1P
  B67_L1N
  B67_L6P
  B67_L6N
  B67_L3P
  B67_L3N
- Title
- Size:
- Date:
- C
- Number:
- Time:
- Revision:
- Sheet
- of

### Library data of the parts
C3 C5 C10 C30-C34 = 000070: Partnumber: 000070; manufacturer: Kemet; manufacturer_pn: C0402C104K8PACTU; ValueFloat: 1E-7; id: 750; inventory_price: 0.0023; reorder_quantity: 70000; x_tolerance: 10
J3 = 001604: 0.8mm hi-speed, high-density header (male); Partnumber: 001604; Manufacturer: Samtec; Description 2: 40-pin, ground protection in middle
J10 = 001335: U.FL surface-mount coaxial connector; Manufacturer: Hirose; Manufacturer_PN: U.FL-R-SMT-1; partnumber: 001335; x_lifecycle_status: Production
J16 = 001334: PartNumber: 001334; manufacturer: 3M; manufacturer_pn: 951120-8622-AR; id: 98023; inventory_price: 0.924
MC1 = 000876: 0.5mm hi-speed, high-density header (Female); Partnumber: 000876; Manufacturer: Samtec; Description 2: 180-pin, ground plane in middle
MC4 = 000583: Partnumber: 000583; manufacturer: Molex; id: 9990; inventory_price: 1.03
Q1 Q3 Q4 = 002018: Partnumber: 002018; manufacturer: Vishay
R1 R34 R54 = 001521: Thick-film resistor; Manufacturer: Vishay; Partnumber: 001521; Description 2: SM-0402, 1%, 1/16W; ValueFloat: 10000; Tolerance (%): 1
R2 R35 R55 = 000964: Thick-film resistor; Partnumber: 000964; Manufacturer: Vishay; ValueFloat: 200000; Tolerance (%): 1; Description 2: SM-0402, 1%, 1/16W
R13-R18 R30-R33 R36-R41 R48-R51 R56-R63 = 001008: Partnumber: 001008; manufacturer: Vishay; ValueFloat: 4750; x_tolerance: 1
R66 = 000934: Thick-film resistor; Partnumber: 000934; Manufacturer: Vishay; ValueFloat: 24900; Tolerance (%): 1; Description 2: SM-0402, 1%, 1/16W
TP23 TP24 = TESTPOINT-SMD20: Test point, surface-mount, 20mil; partnumber: ALIGNI_IGNORE
U3 U5 U8 = 002527: Partnumber: 002527; Manufacturer: NXP
U4 = 002560: Partnumber: 002560; Manufacturer: Abracon; Description 2: 1.8V, enable/disable, 3.2mm x 2.5mm
U11 = 002537: Partnumber: 002537; Manufacturer: ON Semiconductor; Description 2: 600Mbps, 3.3V, SOT23-5

## Sheet MC2.SchDoc: BRK8370 - MC2
size C; Organization: Opal Kelly; Address1: 13500 SW 72nd Ave STE 100; Address2: Portland, OR 97223; Address3: 217.391.3724; Address4: http://www.opalkelly.com; DocumentNumber: 3; Revision: 1; SheetNumber: 3; SheetTotal: 8
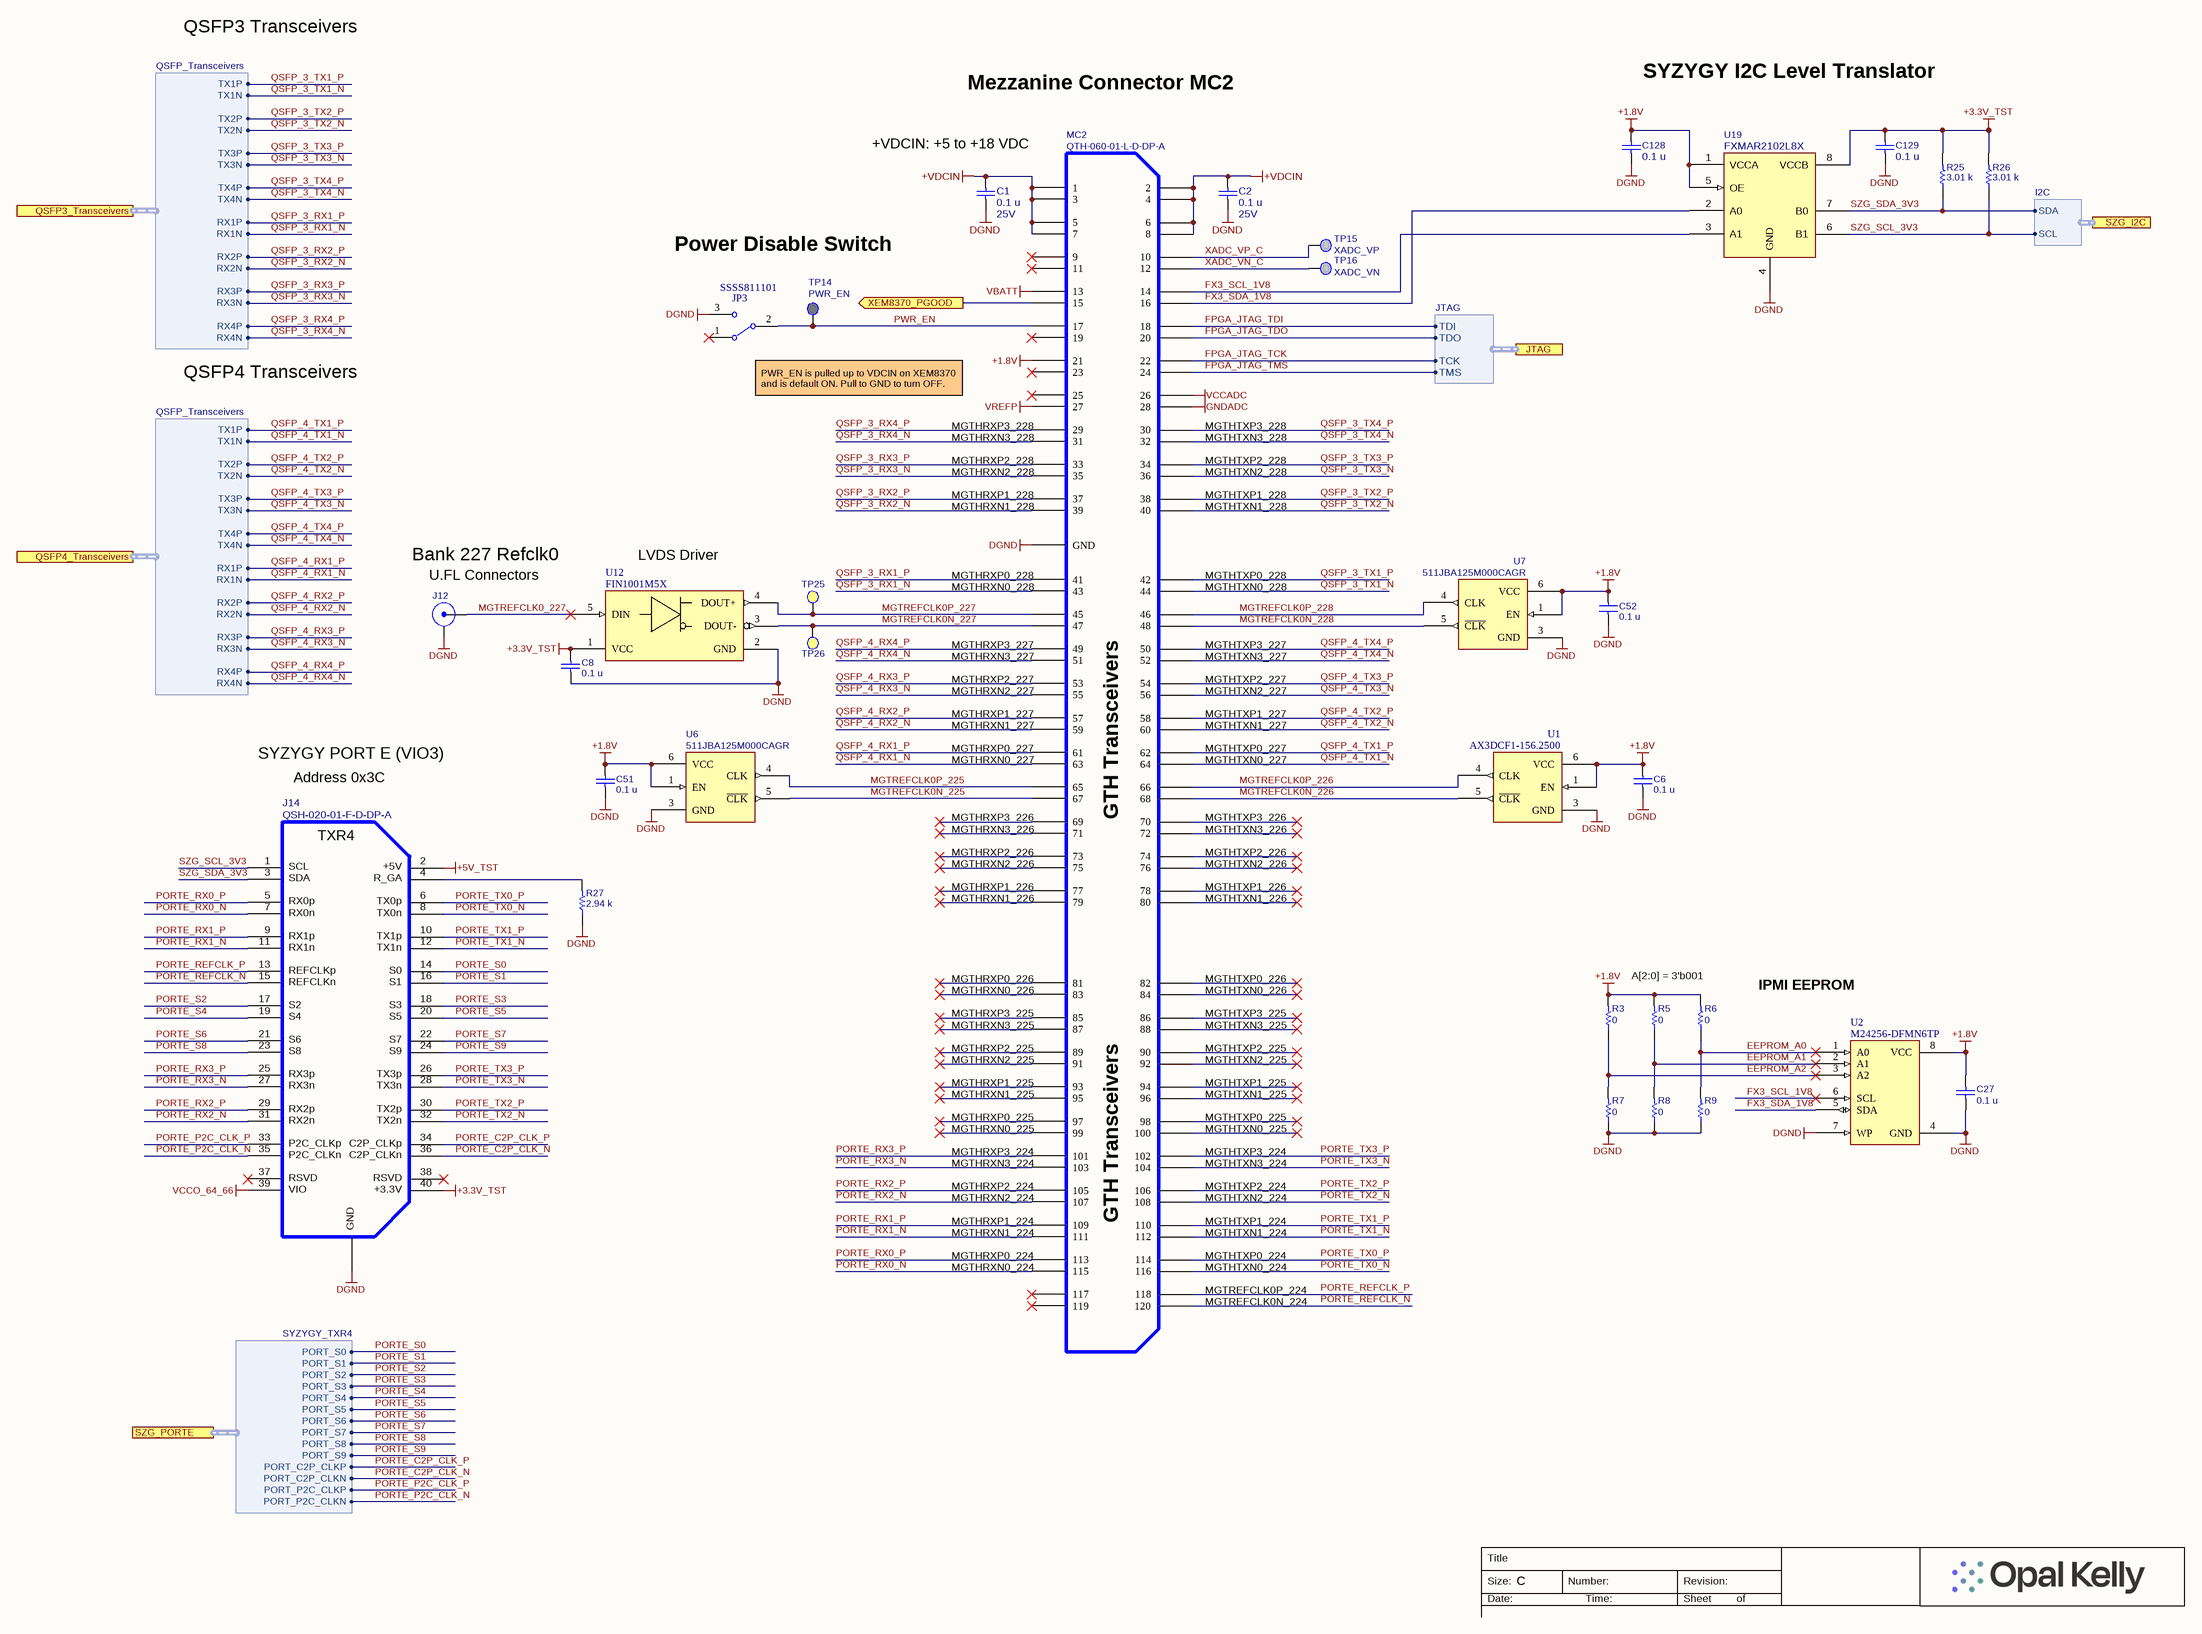
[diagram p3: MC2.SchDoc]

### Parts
C1  value 0.1 u  Voltage: 25V  [CAPC1005X06A]  (hidden comment: TMK105BJ104KV-F)
C2  value 0.1 u  Voltage: 25V  [CAPC1005X06A]  (hidden comment: TMK105BJ104KV-F)
C6  value 0.1 u  [CAPC1005X06A]  (hidden comment: SM-0402, 10%, 10v)
C8  value 0.1 u  [CAPC1005X06A]  (hidden comment: SM-0402, 10%, 10v)
C27  value 0.1 u  [CAPC1005X06A]  (hidden comment: C0402C104K8PACTU)
C51  value 0.1 u  [CAPC1005X06A]  (hidden comment: SM-0402, 10%, 10v)
C52  value 0.1 u  [CAPC1005X06A]  (hidden comment: SM-0402, 10%, 10v)
C128  value 0.1 u  [CAPC1005X06A]  (hidden comment: C0402C104K8PACTU)
C129  value 0.1 u  [CAPC1005X06A]  (hidden comment: C0402C104K8PACTU)
J12  RXP0  [UFL-R-SMT-1]  (value not drawn)
J14  QSH-020-01-F-D-DP-A  [QSH-020-01-X-D-DP-A-L-SYZYGY]
JP3  SSSS811101  [SSSS811101]
MC2  QTH-060-01-L-D-DP-A  [QTH-060-01-X-D-DP-A]
R3  value 0  [RESC1005X06A]  (hidden comment: CRCW04020000Z0ED)
R5  value 0  [RESC1005X06A]  (hidden comment: CRCW04020000Z0ED)
R6  value 0  [RESC1005X06A]  (hidden comment: CRCW04020000Z0ED)
R7  value 0  [RESC1005X06A]  (hidden comment: CRCW04020000Z0ED)
R8  value 0  [RESC1005X06A]  (hidden comment: CRCW04020000Z0ED)
R9  value 0  [RESC1005X06A]  (hidden comment: CRCW04020000Z0ED)
R25  value 3.01 k  [RESC1005X06A]  (hidden comment: CRCW04023K01FKED)
R26  value 3.01 k  [RESC1005X06A]  (hidden comment: CRCW04023K01FKED)
R27  value 2.94 k  [RESC1005N]  (hidden comment: CRCW04022K94FKED)
TP14  PWR_EN  [TP-PTH-65/100]
TP15  XADC_VP  [TP-PTH-25/45]
TP16  XADC_VN  [TP-PTH-25/45]
TP25  TESTPOINT-SMD20  [TP-SMD20]  (value not drawn)
TP26  TESTPOINT-SMD20  [TP-SMD20]  (value not drawn)
U1  AX3DCF1-156.2500  [OSC_SMD_32x25_6pin]
U2  M24256-DFMN6TP  [SO-G8]
U6  511JBA125M000CAGR  [OSC_SMD_32x25_6pin]
U7  511JBA125M000CAGR  [OSC_SMD_32x25_6pin]
U12  FIN1001M5X  [SOT23-5]
U19  FXMAR2102L8X  [FXMAR2102L8X]

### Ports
JTAG (harness JTAG), QSFP3_Transceivers (harness QSFP_Transceivers), QSFP4_Transceivers (harness QSFP_Transceivers), SZG_I2C (harness I2C), SZG_PORTE (harness SYZYGY_TXR4), XEM8370_PGOOD (out)

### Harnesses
QSFP_Transceivers: TX1P, TX1N, TX2P, TX2N, TX3P, TX3N, TX4P, TX4N, RX1P, RX1N, RX2P, RX2N, RX3P, RX3N, RX4P, RX4N
I2C: SCL, SDA
SYZYGY_TXR4: PORT_S0, PORT_S1, PORT_S2, PORT_S3, PORT_S4, PORT_S5, PORT_S6, PORT_S7, PORT_S8, PORT_S9, PORT_C2P_CLKP, PORT_C2P_CLKN, PORT_P2C_CLKP, PORT_P2C_CLKN
JTAG: TDI, TDO, TCK, TMS

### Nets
+1.8V: C6.2 C27.2 C51.2 C52.2 C128.2 MC2.21 R3.2 R5.2 R6.2 U1.1(EN) U1.6(VCC) U2.8(VCC) U6.1(EN) U6.6(VCC) U7.1(EN) U7.6(VCC) U19.1(VCCA) U19.5(OE)
+3.3V_TST: C8.2 C129.2 J14.40 R25.2 R26.2 U12.1(VCC) U19.8(VCCB)
+5V_TST: J14.2
+VDCIN: C1.1 C2.1 MC2.1 MC2.2 MC2.3 MC2.4 MC2.5 MC2.6 MC2.7 MC2.8
DGND: C1.2 C2.2 C6.1 C8.1 C27.1 C51.1 C52.1 C128.1 C129.1 J12.2(GND) J14.0(GND) JP3.3 MC2.0(GND) R7.1 R8.1 R9.1 R27.1 U1.3(GND) U2.4(GND) U2.7(WP) U6.3(GND) U7.3(GND) U12.2(GND) U19.4(GND)
GNDADC: MC2.28
VBATT: MC2.13
VCCADC: MC2.26
VCCO_64_66: J14.39
VREFP: MC2.27
EEPROM_A0: R6.1 R9.2 U2.1(A0)
EEPROM_A1: R5.1 R8.2 U2.2(A1)
EEPROM_A2: R3.1 R7.2 U2.3(A2)
FPGA_JTAG_TCK: MC2.22 ; port JTAG.TCK
FPGA_JTAG_TDI: MC2.18 ; port JTAG.TDI
FPGA_JTAG_TDO: MC2.20 ; port JTAG.TDO
FPGA_JTAG_TMS: MC2.24 ; port JTAG.TMS
FX3_SCL_1V8: MC2.14 U2.6(SCL) U19.3(A1)
FX3_SDA_1V8: MC2.16 U2.5(SDA) U19.2(A0)
MGTREFCLK0_227: J12.1(SIGNAL) U12.5(DIN)
MGTREFCLK0N_225: MC2.67 U6.5(~{CLK})
MGTREFCLK0N_226: MC2.68 U1.5(~{CLK})
MGTREFCLK0N_227: MC2.47 TP26.1(PIN) U12.3(DOUT-)
MGTREFCLK0N_228: MC2.48 U7.5(~{CLK})
MGTREFCLK0P_225: MC2.65 U6.4(CLK)
MGTREFCLK0P_226: MC2.66 U1.4(CLK)
MGTREFCLK0P_227: MC2.45 TP25.1(PIN) U12.4(DOUT+)
MGTREFCLK0P_228: MC2.46 U7.4(CLK)
PORTE_C2P_CLK_N: J14.36 ; port SZG_PORTE.PORT_C2P_CLKN
PORTE_C2P_CLK_P: J14.34 ; port SZG_PORTE.PORT_C2P_CLKP
PORTE_P2C_CLK_N: J14.35 ; port SZG_PORTE.PORT_P2C_CLKN
PORTE_P2C_CLK_P: J14.33 ; port SZG_PORTE.PORT_P2C_CLKP
PORTE_REFCLK_N: J14.15 MC2.120
PORTE_REFCLK_P: J14.13 MC2.118
PORTE_RX0_N: J14.7 MC2.115
PORTE_RX0_P: J14.5 MC2.113
PORTE_RX1_N: J14.11 MC2.111
PORTE_RX1_P: J14.9 MC2.109
PORTE_RX2_N: J14.31 MC2.107
PORTE_RX2_P: J14.29 MC2.105
PORTE_RX3_N: J14.27 MC2.103
PORTE_RX3_P: J14.25 MC2.101
PORTE_S0: J14.14 ; port SZG_PORTE.PORT_S0
PORTE_S1: J14.16 ; port SZG_PORTE.PORT_S1
PORTE_S2: J14.17 ; port SZG_PORTE.PORT_S2
PORTE_S3: J14.18 ; port SZG_PORTE.PORT_S3
PORTE_S4: J14.19 ; port SZG_PORTE.PORT_S4
PORTE_S5: J14.20 ; port SZG_PORTE.PORT_S5
PORTE_S6: J14.21 ; port SZG_PORTE.PORT_S6
PORTE_S7: J14.22 ; port SZG_PORTE.PORT_S7
PORTE_S8: J14.23 ; port SZG_PORTE.PORT_S8
PORTE_S9: J14.24 ; port SZG_PORTE.PORT_S9
PORTE_TX0_N: J14.8 MC2.116
PORTE_TX0_P: J14.6 MC2.114
PORTE_TX1_N: J14.12 MC2.112
PORTE_TX1_P: J14.10 MC2.110
PORTE_TX2_N: J14.32 MC2.108
PORTE_TX2_P: J14.30 MC2.106
PORTE_TX3_N: J14.28 MC2.104
PORTE_TX3_P: J14.26 MC2.102
PWR_EN: JP3.2 MC2.17 TP14.1(PIN)
QSFP_3_RX1_N: MC2.43 ; port QSFP3_Transceivers.RX1N
QSFP_3_RX1_P: MC2.41 ; port QSFP3_Transceivers.RX1P
QSFP_3_RX2_N: MC2.39 ; port QSFP3_Transceivers.RX2N
QSFP_3_RX2_P: MC2.37 ; port QSFP3_Transceivers.RX2P
QSFP_3_RX3_N: MC2.35 ; port QSFP3_Transceivers.RX3N
QSFP_3_RX3_P: MC2.33 ; port QSFP3_Transceivers.RX3P
QSFP_3_RX4_N: MC2.31 ; port QSFP3_Transceivers.RX4N
QSFP_3_RX4_P: MC2.29 ; port QSFP3_Transceivers.RX4P
QSFP_3_TX1_N: MC2.44 ; port QSFP3_Transceivers.TX1N
QSFP_3_TX1_P: MC2.42 ; port QSFP3_Transceivers.TX1P
QSFP_3_TX2_N: MC2.40 ; port QSFP3_Transceivers.TX2N
QSFP_3_TX2_P: MC2.38 ; port QSFP3_Transceivers.TX2P
QSFP_3_TX3_N: MC2.36 ; port QSFP3_Transceivers.TX3N
QSFP_3_TX3_P: MC2.34 ; port QSFP3_Transceivers.TX3P
QSFP_3_TX4_N: MC2.32 ; port QSFP3_Transceivers.TX4N
QSFP_3_TX4_P: MC2.30 ; port QSFP3_Transceivers.TX4P
QSFP_4_RX1_N: MC2.63 ; port QSFP4_Transceivers.RX1N
QSFP_4_RX1_P: MC2.61 ; port QSFP4_Transceivers.RX1P
QSFP_4_RX2_N: MC2.59 ; port QSFP4_Transceivers.RX2N
QSFP_4_RX2_P: MC2.57 ; port QSFP4_Transceivers.RX2P
QSFP_4_RX3_N: MC2.55 ; port QSFP4_Transceivers.RX3N
QSFP_4_RX3_P: MC2.53 ; port QSFP4_Transceivers.RX3P
QSFP_4_RX4_N: MC2.51 ; port QSFP4_Transceivers.RX4N
QSFP_4_RX4_P: MC2.49 ; port QSFP4_Transceivers.RX4P
QSFP_4_TX1_N: MC2.64 ; port QSFP4_Transceivers.TX1N
QSFP_4_TX1_P: MC2.62 ; port QSFP4_Transceivers.TX1P
QSFP_4_TX2_N: MC2.60 ; port QSFP4_Transceivers.TX2N
QSFP_4_TX2_P: MC2.58 ; port QSFP4_Transceivers.TX2P
QSFP_4_TX3_N: MC2.56 ; port QSFP4_Transceivers.TX3N
QSFP_4_TX3_P: MC2.54 ; port QSFP4_Transceivers.TX3P
QSFP_4_TX4_N: MC2.52 ; port QSFP4_Transceivers.TX4N
QSFP_4_TX4_P: MC2.50 ; port QSFP4_Transceivers.TX4P
SZG_SCL_3V3: J14.1 R26.1 U19.6(B1) ; port SZG_I2C.SCL
SZG_SDA_3V3: J14.3 R25.1 U19.7(B0) ; port SZG_I2C.SDA
XADC_VN_C: MC2.12 TP16.1(PIN)
XADC_VP_C: MC2.10 TP15.1(PIN)
XEM8370_PGOOD: MC2.15 ; port XEM8370_PGOOD
NetJ14_4: J14.4 R27.2

Not connected (* = marked no-connect by the designer): J14 37* 38*; JP3 1*; MC2 9* 11* 19* 23* 25* 69* 70* 71* 72* 73* 74* 75* 76* 77* 78* 79* 80* 81* 82* 83* 84* 85* 86* 87* 88* 89* 90* 91* 92* 93* 94* 95* 96* 97* 98* 99* 100* 117* 119*

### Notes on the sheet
- QSFP3 Transceivers
- Mezzanine Connector MC2
- SYZYGY I2C Level Translator
- +VDCIN: +5 to +18 VDC
- Power Disable Switch
- QSFP4 Transceivers
- (near JP3) PWR_EN is pulled up to VDCIN on XEM8370 and is default ON. Pull to GND to turn OFF.
- Bank 227 Refclk0
- (near J12) U.FL Connectors
- (near U12) LVDS Driver
- (near MC2) GTH Transceivers
- Address 0x3C
- SYZYGY PORT E (VIO3)
- A[2:0] = 3'b001
- IPMI EEPROM
- (near MC2) MGTHRXP3_228
  MGTHRXN3_228
  MGTHRXP2_228
  MGTHRXN2_228
  MGTHRXP1_228
  MGTHRXN1_228
  MGTHRXP0_228
  MGTHRXN0_228
  MGTHRXP3_227
  MGTHRXN3_227
  MGTHRXP2_227
  MGTHRXN2_227
  MGTHRXP1_227
  MGTHRXN1_227
  MGTHRXP0_227
  MGTHRXN0_227
  MGTHRXP3_226
  MGTHRXN3_226
  MGTHRXP2_226
  MGTHRXN2_226
  MGTHRXP1_226
  MGTHRXN1_226
  MGTHRXP0_226
  MGTHRXN0_226
  MGTHRXP3_225
  MGTHRXN3_225
  MGTHRXP2_225
  MGTHRXN2_225
  MGTHRXP1_225
  MGTHRXN1_225
  MGTHRXP0_225
  MGTHRXN0_225
  MGTHRXP3_224
  MGTHRXN3_224
  MGTHRXP2_224
  MGTHRXN2_224
  MGTHRXP1_224
  MGTHRXN1_224
  MGTHRXP0_224
  MGTHRXN0_224
- MGTHTXP3_228
  MGTHTXN3_228
  MGTHTXP2_228
  MGTHTXN2_228
  MGTHTXP1_228
  MGTHTXN1_228
  MGTHTXP0_228
  MGTHTXN0_228
  MGTHTXP3_227
  MGTHTXN3_227
  MGTHTXP2_227
  MGTHTXN2_227
  MGTHTXP1_227
  MGTHTXN1_227
  MGTHTXP0_227
  MGTHTXN0_227
  MGTHTXP3_226
  MGTHTXN3_226
  MGTHTXP2_226
  MGTHTXN2_226
  MGTHTXP1_226
  MGTHTXN1_226
  MGTHTXP0_226
  MGTHTXN0_226
  MGTHTXP3_225
  MGTHTXN3_225
  MGTHTXP2_225
  MGTHTXN2_225
  MGTHTXP1_225
  MGTHTXN1_225
  MGTHTXP0_225
  MGTHTXN0_225
  MGTHTXP3_224
  MGTHTXN3_224
  MGTHTXP2_224
  MGTHTXN2_224
  MGTHTXP1_224
  MGTHTXN1_224
  MGTHTXP0_224
  MGTHTXN0_224
  MGTREFCLK0P_224
  MGTREFCLK0N_224
- Title
- Size:
- Date:
- C
- Number:
- Time:
- Revision:
- Sheet
- of

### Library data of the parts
C1 C2 = 001073: Ceramic capacitor; Manufacturer: Taiyo Yuden; partnumber: 001073; Description 2: 0402, 25V; ValueFloat: 1E-7; Tolerance (%): 10
C6 C8 C51 C52 = 000070: as C3 on sheet MC1
C27 = 000070: Partnumber: 000070; manufacturer: Kemet; ValueFloat: 1E-7; x_tolerance: 10
C128 C129 = 000070: Ceramic capacitor; Manufacturer: Kemet; partnumber: 000070; Description 2: SM-0402, 10%, 10v; ValueFloat: 1E-7; Tolerance (%): 10
J12 = 001335: as J10 on sheet MC1
J14 = 000694: 0.5mm Double Row High Speed Socket Assembly; Partnumber: 000694; manufacturer: Samtec
JP3 = 000231: Slide; Partnumber: 000231; Manufacturer: Alps; Description 2: 1 position, 2 pole, SMT slide switch
MC2 = 001769: Partnumber: 001769; manufacturer: Samtec
R3 R5-R9 = 000755: Partnumber: 000755; manufacturer: Vishay; x_tolerance: 1
R25 R26 = 001126: Partnumber: 001126; manufacturer: Vishay; ValueFloat: 3010; x_tolerance: 1
R27 = 000927: Thick-film resistor; Partnumber: 000927; Manufacturer: Vishay; ValueFloat: 2940; Tolerance (%): 1; Description 2: SM-0402, 1%, 1/16W
TP14 = TP-PTH-65/100: as TP1 on sheet Top
TP15 TP16 = TP-PTH-25/45: as TP2 on sheet Top
TP25 TP26 = TESTPOINT-SMD20: as TP23 on sheet MC1
U1 = 002560: as U4 on sheet MC1
U2 = 002189: Partnumber: 002189; manufacturer: ST Microelectronics
U6 U7 = 001712: Partnumber: 001712; manufacturer: Silicon Labs; id: 219250; inventory_price: 2.75
U12 = 002537: as U11 on sheet MC1
U19 = 001559: Partnumber: 001559; manufacturer: ON Semiconductor

## Sheet MC3.SchDoc: BRK8370 - MC3
size C; Organization: Opal Kelly; Address1: 13500 SW 72nd Ave STE 100; Address2: Portland, OR 97223; Address3: 217.391.3724; Address4: http://www.opalkelly.com; DocumentNumber: 4; Revision: 1; SheetNumber: 4; SheetTotal: 8
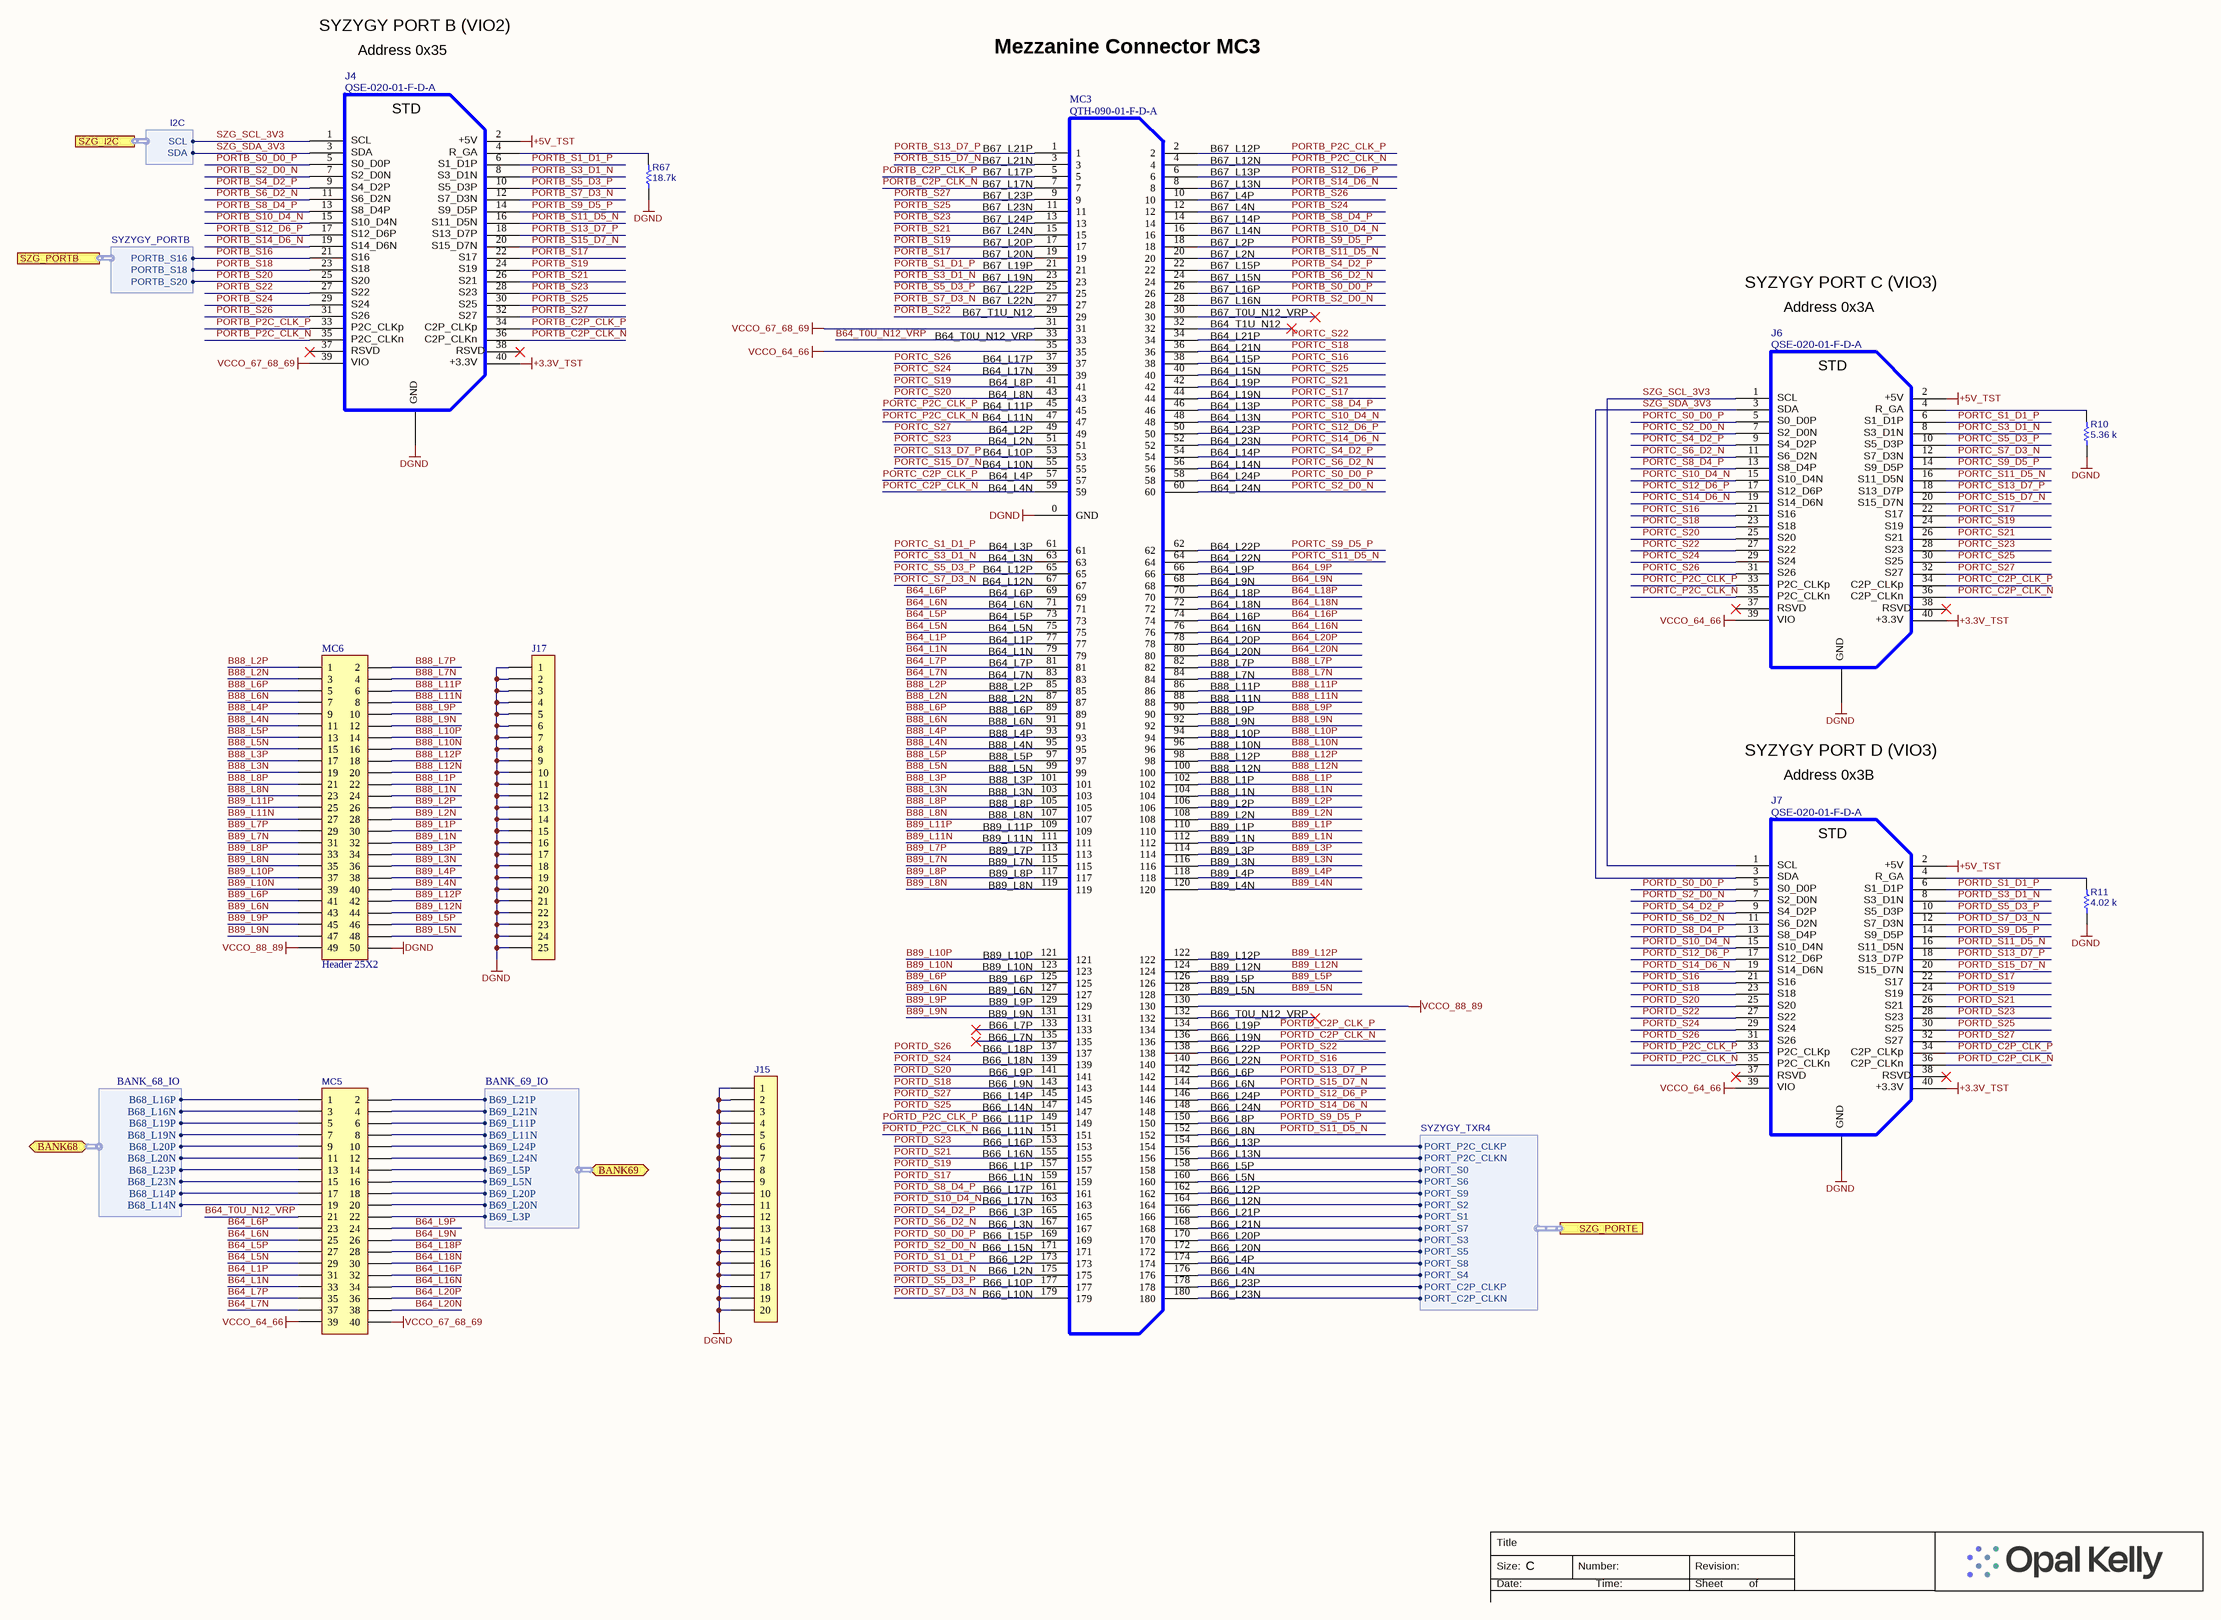
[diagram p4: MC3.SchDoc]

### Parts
J4  QSE-020-01-F-D-A  [QSE-020-01-X-D-A-L-SYZYGY]
J6  QSE-020-01-F-D-A  [QSE-020-01-X-D-A-L-SYZYGY]
J7  QSE-020-01-F-D-A  [QSE-020-01-X-D-A-L-SYZYGY]
J15  Header, 20-Pin, Single Row  [HDR1X20-2MM]  (value not drawn)
J17  Header, 25-Pin, Single Row  [HDR1X25-2MM]  (value not drawn)
MC3  QTH-090-01-F-D-A  [QTH-090-01-X-D]
MC5  0877584016  [HDR2X20-2MM]  (value not drawn)
MC6  Header 25X2  [HDR2X25-2MM]
R10  value 5.36 k  [RESC1005X06A]  (hidden comment: CRCW04025K36FKED)
R11  value 4.02 k  [RESC1005X06A]  (hidden comment: CRCW04024K02FKED)
R67  value 18.7k  [RESC1005X06A]  (hidden comment: CRCW040218K7FKED)

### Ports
BANK68 (bidir, harness BANK_68_IO), BANK69 (bidir, harness BANK_69_IO), SZG_I2C (harness I2C), SZG_PORTB (harness SYZYGY_PORTB), SZG_PORTE (harness SYZYGY_TXR4)

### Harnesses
SYZYGY_TXR4: PORT_S0, PORT_S1, PORT_S2, PORT_S3, PORT_S4, PORT_S5, PORT_S6, PORT_S7, PORT_S8, PORT_S9, PORT_C2P_CLKP, PORT_C2P_CLKN, PORT_P2C_CLKP, PORT_P2C_CLKN
I2C: SCL, SDA
BANK_69_IO: B69_L21P, B69_L21N, B69_L11P, B69_L11N, B69_L24P, B69_L24N, B69_L5P, B69_L5N, B69_L20P, B69_L20N, B69_L3P
BANK_68_IO: B68_L20P, B68_L20N, B68_L23P, B68_L23N, B68_L14P, B68_L14N, B68_L16P, B68_L16N, B68_L19P, B68_L19N
SYZYGY_PORTB: PORTB_S20, PORTB_S16, PORTB_S18

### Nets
+3.3V_TST: J4.40 J6.40 J7.40
+5V_TST: J4.2 J6.2 J7.2
DGND: J4.0 J6.0 J7.0 J15.1 J15.2 J15.3 J15.4 J15.5 J15.6 J15.7 J15.8 J15.9 J15.10 J15.11 J15.12 J15.13 J15.14 J15.15 J15.16 J15.17 J15.18 J15.19 J15.20 J17.1 J17.2 J17.3 J17.4 J17.5 J17.6 J17.7 J17.8 J17.9 J17.10 J17.11 J17.12 J17.13 J17.14 J17.15 J17.16 J17.17 J17.18 J17.19 J17.20 J17.21 J17.22 J17.23 J17.24 J17.25 MC3.0(GND) MC6.50 R10.1 R11.1 R67.1
VCCO_64_66: J6.39 J7.39 MC3.35 MC5.39
VCCO_67_68_69: J4.39 MC3.31 MC5.40
VCCO_88_89: MC3.130 MC6.49
B64_L1N: MC3.79 MC5.33
B64_L1P: MC3.77 MC5.31
B64_L5N: MC3.75 MC5.29
B64_L5P: MC3.73 MC5.27
B64_L6N: MC3.71 MC5.25
B64_L6P: MC3.69 MC5.23
B64_L7N: MC3.83 MC5.37
B64_L7P: MC3.81 MC5.35
B64_L9N: MC3.68 MC5.26
B64_L9P: MC3.66 MC5.24
B64_L16N: MC3.76 MC5.34
B64_L16P: MC3.74 MC5.32
B64_L18N: MC3.72 MC5.30
B64_L18P: MC3.70 MC5.28
B64_L20N: MC3.80 MC5.38
B64_L20P: MC3.78 MC5.36
B64_T0U_N12_VRP: MC3.33 MC5.21
B68_L14N: MC5.19 ; port BANK68.B68_L14N
B68_L14P: MC5.17 ; port BANK68.B68_L14P
B68_L16N: MC5.3 ; port BANK68.B68_L16N
B68_L16P: MC5.1 ; port BANK68.B68_L16P
B68_L19N: MC5.7 ; port BANK68.B68_L19N
B68_L19P: MC5.5 ; port BANK68.B68_L19P
B68_L20N: MC5.11 ; port BANK68.B68_L20N
B68_L20P: MC5.9 ; port BANK68.B68_L20P
B68_L23N: MC5.15 ; port BANK68.B68_L23N
B68_L23P: MC5.13 ; port BANK68.B68_L23P
B69_L3P: MC5.22 ; port BANK69.B69_L3P
B69_L5N: MC5.16 ; port BANK69.B69_L5N
B69_L5P: MC5.14 ; port BANK69.B69_L5P
B69_L11N: MC5.8 ; port BANK69.B69_L11N
B69_L11P: MC5.6 ; port BANK69.B69_L11P
B69_L20N: MC5.20 ; port BANK69.B69_L20N
B69_L20P: MC5.18 ; port BANK69.B69_L20P
B69_L21N: MC5.4 ; port BANK69.B69_L21N
B69_L21P: MC5.2 ; port BANK69.B69_L21P
B69_L24N: MC5.12 ; port BANK69.B69_L24N
B69_L24P: MC5.10 ; port BANK69.B69_L24P
B88_L1N: MC3.104 MC6.24
B88_L1P: MC3.102 MC6.22
B88_L2N: MC3.87 MC6.3
B88_L2P: MC3.85 MC6.1
B88_L3N: MC3.103 MC6.19
B88_L3P: MC3.101 MC6.17
B88_L4N: MC3.95 MC6.11
B88_L4P: MC3.93 MC6.9
B88_L5N: MC3.99 MC6.15
B88_L5P: MC3.97 MC6.13
B88_L6N: MC3.91 MC6.7
B88_L6P: MC3.89 MC6.5
B88_L7N: MC3.84 MC6.4
B88_L7P: MC3.82 MC6.2
B88_L8N: MC3.107 MC6.23
B88_L8P: MC3.105 MC6.21
B88_L9N: MC3.92 MC6.12
B88_L9P: MC3.90 MC6.10
B88_L10N: MC3.96 MC6.16
B88_L10P: MC3.94 MC6.14
B88_L11N: MC3.88 MC6.8
B88_L11P: MC3.86 MC6.6
B88_L12N: MC3.100 MC6.20
B88_L12P: MC3.98 MC6.18
B89_L1N: MC3.112 MC6.32
B89_L1P: MC3.110 MC6.30
B89_L2N: MC3.108 MC6.28
B89_L2P: MC3.106 MC6.26
B89_L3N: MC3.116 MC6.36
B89_L3P: MC3.114 MC6.34
B89_L4N: MC3.120 MC6.40
B89_L4P: MC3.118 MC6.38
B89_L5N: MC3.128 MC6.48
B89_L5P: MC3.126 MC6.46
B89_L6N: MC3.127 MC6.43
B89_L6P: MC3.125 MC6.41
B89_L7N: MC3.115 MC6.31
B89_L7P: MC3.113 MC6.29
B89_L8N: MC3.119 MC6.35
B89_L8P: MC3.117 MC6.33
B89_L9N: MC3.131 MC6.47
B89_L9P: MC3.129 MC6.45
B89_L10N: MC3.123 MC6.39
B89_L10P: MC3.121 MC6.37
B89_L11N: MC3.111 MC6.27
B89_L11P: MC3.109 MC6.25
B89_L12N: MC3.124 MC6.44
B89_L12P: MC3.122 MC6.42
PORTB_C2P_CLK_N: J4.36 MC3.7
PORTB_C2P_CLK_P: J4.34 MC3.5
PORTB_P2C_CLK_N: J4.35 MC3.4
PORTB_P2C_CLK_P: J4.33 MC3.2
PORTB_S0_D0_P: J4.5 MC3.26
PORTB_S1_D1_P: J4.6 MC3.21
PORTB_S2_D0_N: J4.7 MC3.28
PORTB_S3_D1_N: J4.8 MC3.23
PORTB_S4_D2_P: J4.9 MC3.22
PORTB_S5_D3_P: J4.10 MC3.25
PORTB_S6_D2_N: J4.11 MC3.24
PORTB_S7_D3_N: J4.12 MC3.27
PORTB_S8_D4_P: J4.13 MC3.14
PORTB_S9_D5_P: J4.14 MC3.18
PORTB_S10_D4_N: J4.15 MC3.16
PORTB_S11_D5_N: J4.16 MC3.20
PORTB_S12_D6_P: J4.17 MC3.6
PORTB_S13_D7_P: J4.18 MC3.1
PORTB_S14_D6_N: J4.19 MC3.8
PORTB_S15_D7_N: J4.20 MC3.3
PORTB_S16: J4.21 ; port SZG_PORTB.PORTB_S16
PORTB_S17: J4.22 MC3.19
PORTB_S18: J4.23 ; port SZG_PORTB.PORTB_S18
PORTB_S19: J4.24 MC3.17
PORTB_S20: J4.25 ; port SZG_PORTB.PORTB_S20
PORTB_S21: J4.26 MC3.15
PORTB_S22: J4.27 MC3.29
PORTB_S23: J4.28 MC3.13
PORTB_S24: J4.29 MC3.12
PORTB_S25: J4.30 MC3.11
PORTB_S26: J4.31 MC3.10
PORTB_S27: J4.32 MC3.9
PORTC_C2P_CLK_N: J6.36 MC3.59
PORTC_C2P_CLK_P: J6.34 MC3.57
PORTC_P2C_CLK_N: J6.35 MC3.47
PORTC_P2C_CLK_P: J6.33 MC3.45
PORTC_S0_D0_P: J6.5 MC3.58
PORTC_S1_D1_P: J6.6 MC3.61
PORTC_S2_D0_N: J6.7 MC3.60
PORTC_S3_D1_N: J6.8 MC3.63
PORTC_S4_D2_P: J6.9 MC3.54
PORTC_S5_D3_P: J6.10 MC3.65
PORTC_S6_D2_N: J6.11 MC3.56
PORTC_S7_D3_N: J6.12 MC3.67
PORTC_S8_D4_P: J6.13 MC3.46
PORTC_S9_D5_P: J6.14 MC3.62
PORTC_S10_D4_N: J6.15 MC3.48
PORTC_S11_D5_N: J6.16 MC3.64
PORTC_S12_D6_P: J6.17 MC3.50
PORTC_S13_D7_P: J6.18 MC3.53
PORTC_S14_D6_N: J6.19 MC3.52
PORTC_S15_D7_N: J6.20 MC3.55
PORTC_S16: J6.21 MC3.38
PORTC_S17: J6.22 MC3.44
PORTC_S18: J6.23 MC3.36
PORTC_S19: J6.24 MC3.41
PORTC_S20: J6.25 MC3.43
PORTC_S21: J6.26 MC3.42
PORTC_S22: J6.27 MC3.34
PORTC_S23: J6.28 MC3.51
PORTC_S24: J6.29 MC3.39
PORTC_S25: J6.30 MC3.40
PORTC_S26: J6.31 MC3.37
PORTC_S27: J6.32 MC3.49
PORTD_C2P_CLK_N: J7.36 MC3.136
PORTD_C2P_CLK_P: J7.34 MC3.134
PORTD_P2C_CLK_N: J7.35 MC3.151
PORTD_P2C_CLK_P: J7.33 MC3.149
PORTD_S0_D0_P: J7.5 MC3.169
PORTD_S1_D1_P: J7.6 MC3.173
PORTD_S2_D0_N: J7.7 MC3.171
PORTD_S3_D1_N: J7.8 MC3.175
PORTD_S4_D2_P: J7.9 MC3.165
PORTD_S5_D3_P: J7.10 MC3.177
PORTD_S6_D2_N: J7.11 MC3.167
PORTD_S7_D3_N: J7.12 MC3.179
PORTD_S8_D4_P: J7.13 MC3.161
PORTD_S9_D5_P: J7.14 MC3.150
PORTD_S10_D4_N: J7.15 MC3.163
PORTD_S11_D5_N: J7.16 MC3.152
PORTD_S12_D6_P: J7.17 MC3.146
PORTD_S13_D7_P: J7.18 MC3.142
PORTD_S14_D6_N: J7.19 MC3.148
PORTD_S15_D7_N: J7.20 MC3.144
PORTD_S16: J7.21 MC3.140
PORTD_S17: J7.22 MC3.159
PORTD_S18: J7.23 MC3.143
PORTD_S19: J7.24 MC3.157
PORTD_S20: J7.25 MC3.141
PORTD_S21: J7.26 MC3.155
PORTD_S22: J7.27 MC3.138
PORTD_S23: J7.28 MC3.153
PORTD_S24: J7.29 MC3.139
PORTD_S25: J7.30 MC3.147
PORTD_S26: J7.31 MC3.137
PORTD_S27: J7.32 MC3.145
PORTE_C2P_CLK_N: MC3.180 ; port SZG_PORTE.PORT_C2P_CLKN
PORTE_C2P_CLK_P: MC3.178 ; port SZG_PORTE.PORT_C2P_CLKP
PORTE_P2C_CLK_N: MC3.156 ; port SZG_PORTE.PORT_P2C_CLKN
PORTE_P2C_CLK_P: MC3.154 ; port SZG_PORTE.PORT_P2C_CLKP
PORTE_S0: MC3.158 ; port SZG_PORTE.PORT_S0
PORTE_S1: MC3.166 ; port SZG_PORTE.PORT_S1
PORTE_S2: MC3.164 ; port SZG_PORTE.PORT_S2
PORTE_S3: MC3.170 ; port SZG_PORTE.PORT_S3
PORTE_S4: MC3.176 ; port SZG_PORTE.PORT_S4
PORTE_S5: MC3.172 ; port SZG_PORTE.PORT_S5
PORTE_S6: MC3.160 ; port SZG_PORTE.PORT_S6
PORTE_S7: MC3.168 ; port SZG_PORTE.PORT_S7
PORTE_S8: MC3.174 ; port SZG_PORTE.PORT_S8
PORTE_S9: MC3.162 ; port SZG_PORTE.PORT_S9
SZG_SCL_3V3: J4.1 J6.1 J7.1 ; port SZG_I2C.SCL
SZG_SDA_3V3: J4.3 J6.3 J7.3 ; port SZG_I2C.SDA
NetJ4_4: J4.4 R67.2
NetJ6_4: J6.4 R10.2
NetJ7_4: J7.4 R11.2

Not connected (* = marked no-connect by the designer): J4 37* 38*; J6 37* 38*; J7 37* 38*; MC3 30* 32* 132* 133* 135*

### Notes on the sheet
- Address 0x35
- SYZYGY PORT B (VIO2)
- Mezzanine Connector MC3
- Address 0x3A
- SYZYGY PORT C (VIO3)
- Address 0x3B
- SYZYGY PORT D (VIO3)
- B67_L12P
  B67_L12N
  B67_L13P
  B67_L13N
  B67_L4P
  B67_L4N
  B67_L14P
  B67_L14N
  B67_L2P
  B67_L2N
  B67_L15P
  B67_L15N
  B67_L16P
  B67_L16N
  B67_T0U_N12_VRP
  B64_T1U_N12
  B64_L21P
  B64_L21N
  B64_L15P
  B64_L15N
  B64_L19P
  B64_L19N
  B64_L13P
  B64_L13N
  B64_L23P
  B64_L23N
  B64_L14P
  B64_L14N
  B64_L24P
  B64_L24N
  B64_L22P
  B64_L22N
  B64_L9P
  B64_L9N
  B64_L18P
  B64_L18N
  B64_L16P
  B64_L16N
  B64_L20P
  B64_L20N
  B88_L7P
  B88_L7N
  B88_L11P
  B88_L11N
  B88_L9P
  B88_L9N
  B88_L10P
  B88_L10N
  B88_L12P
  B88_L12N
  B88_L1P
  B88_L1N
  B89_L2P
  B89_L2N
  B89_L1P
  B89_L1N
  B89_L3P
  B89_L3N
  B89_L4P
  B89_L4N
  B89_L12P
  B89_L12N
  B89_L5P
  B89_L5N
  B66_T0U_N12_VRP
  B66_L19P
  B66_L19N
  B66_L22P
  B66_L22N
  B66_L6P
  B66_L6N
  B66_L24P
  B66_L24N
  B66_L8P
  B66_L8N
  B66_L13P
  B66_L13N
  B66_L5P
  B66_L5N
  B66_L12P
  B66_L12N
  B66_L21P
  B66_L21N
  B66_L20P
  B66_L20N
  B66_L4P
  B66_L4N
  B66_L23P
  B66_L23N
- (near MC3) B67_L21P
  B67_L21N
  B67_L17P
  B67_L17N
  B67_L23P
  B67_L23N
  B67_L24P
  B67_L24N
  B67_L20P
  B67_L20N
  B67_L19P
  B67_L19N
  B67_L22P
  B67_L22N
  B67_T1U_N12
  B64_T0U_N12_VRP
  B64_L17P
  B64_L17N
  B64_L8P
  B64_L8N
  B64_L11P
  B64_L11N
  B64_L2P
  B64_L2N
  B64_L10P
  B64_L10N
  B64_L4P
  B64_L4N
  B64_L3P
  B64_L3N
  B64_L12P
  B64_L12N
  B64_L6P
  B64_L6N
  B64_L5P
  B64_L5N
  B64_L1P
  B64_L1N
  B64_L7P
  B64_L7N
  B88_L2P
  B88_L2N
  B88_L6P
  B88_L6N
  B88_L4P
  B88_L4N
  B88_L5P
  B88_L5N
  B88_L3P
  B88_L3N
  B88_L8P
  B88_L8N
  B89_L11P
  B89_L11N
  B89_L7P
  B89_L7N
  B89_L8P
  B89_L8N
  B89_L10P
  B89_L10N
  B89_L6P
  B89_L6N
  B89_L9P
  B89_L9N
  B66_L7P
  B66_L7N
  B66_L18P
  B66_L18N
  B66_L9P
  B66_L9N
  B66_L14P
  B66_L14N
  B66_L11P
  B66_L11N
  B66_L16P
  B66_L16N
  B66_L1P
  B66_L1N
  B66_L17P
  B66_L17N
  B66_L3P
  B66_L3N
  B66_L15P
  B66_L15N
  B66_L2P
  B66_L2N
  B66_L10P
  B66_L10N
- Title
- Size:
- Date:
- C
- Number:
- Time:
- Revision:
- Sheet
- of

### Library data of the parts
J4 J6 J7 = 001604: as J3 on sheet MC1
J15 = 001334: as J16 on sheet MC1
J17 = 002533: PartNumber: 002533; Manufacturer: 3M; Manufacturer_PN: 951125-8622-AR
MC3 = 000876: as MC1 on sheet MC1
MC5 = 000583: as MC4 on sheet MC1
MC6 = 002532: Manufacturer: Molex; PartNumber: 002532; Manufacturer_PN: 0877585016; Class I: Connector
R10 = 001910: Thick-film resistor; Partnumber: 001910; Manufacturer: Vishay; ValueFloat: 5360; Tolerance (%): 1; Description 2: SM-0402, 1%, 1/16W
R11 = 001007: Thick-film resistor; Partnumber: 001007; Manufacturer: Vishay; ValueFloat: 4020; Tolerance (%): 1; Description 2: SM-0402, 1%, 1/16W
R67 = 001783: Thick-film resistor; Partnumber: 001783; Manufacturer: Vishay; ValueFloat: 18700; Tolerance (%): 1; Description 2: SM-0402, 1%, 1/16W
